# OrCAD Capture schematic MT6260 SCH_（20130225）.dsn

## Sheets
1 99==== Modification List: title: 99 Modify List; rev: V1.0; note: MT6260 PHONE
2 10==== PERI_Audio_USB11: size Custom; title: MT6260; rev: 1A; note: Audio_USB1.1
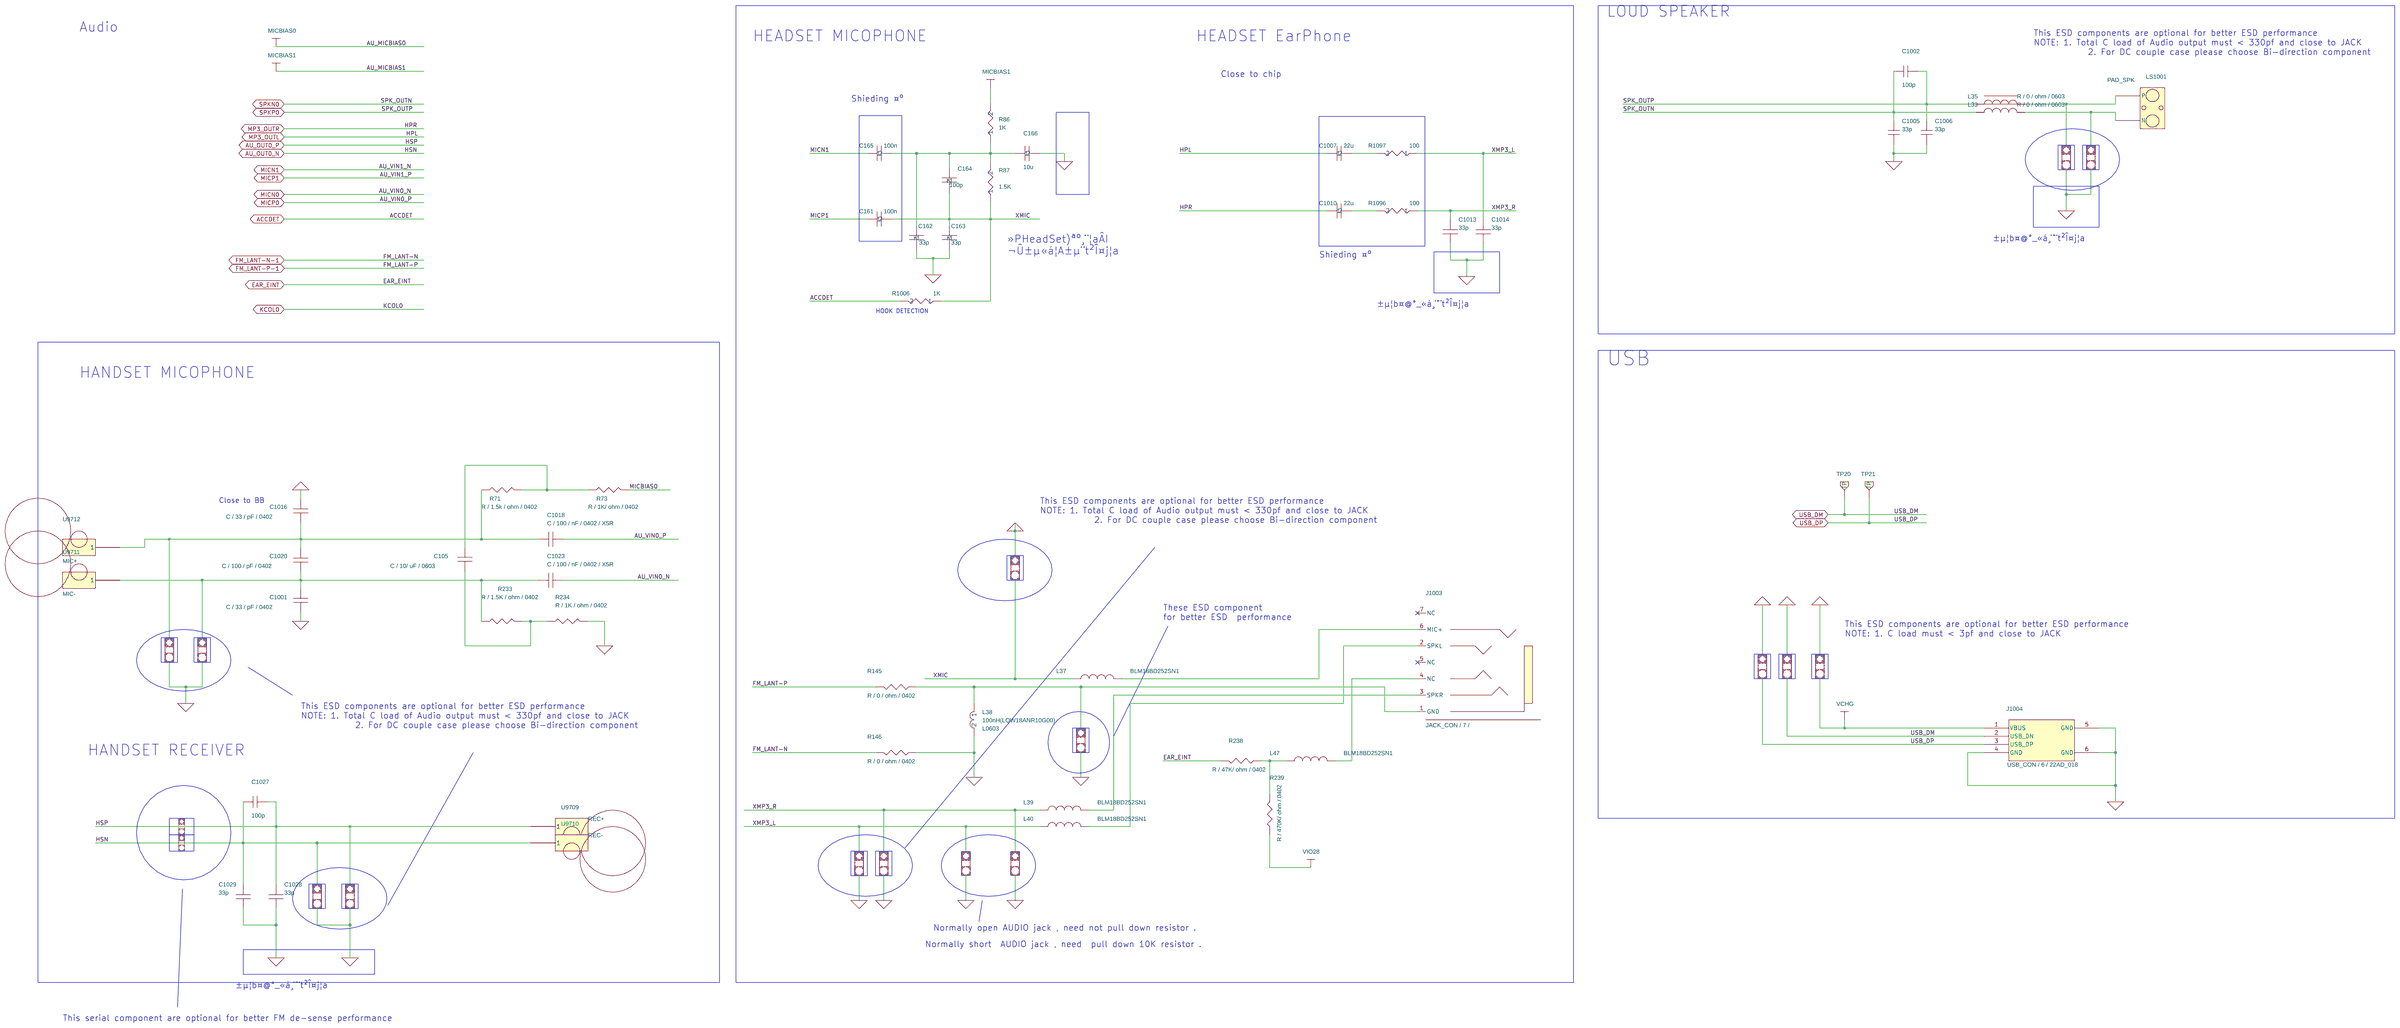
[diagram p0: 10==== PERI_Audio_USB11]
3 01==== History: title: Func. Owner List; rev: 1A; note: Baseband
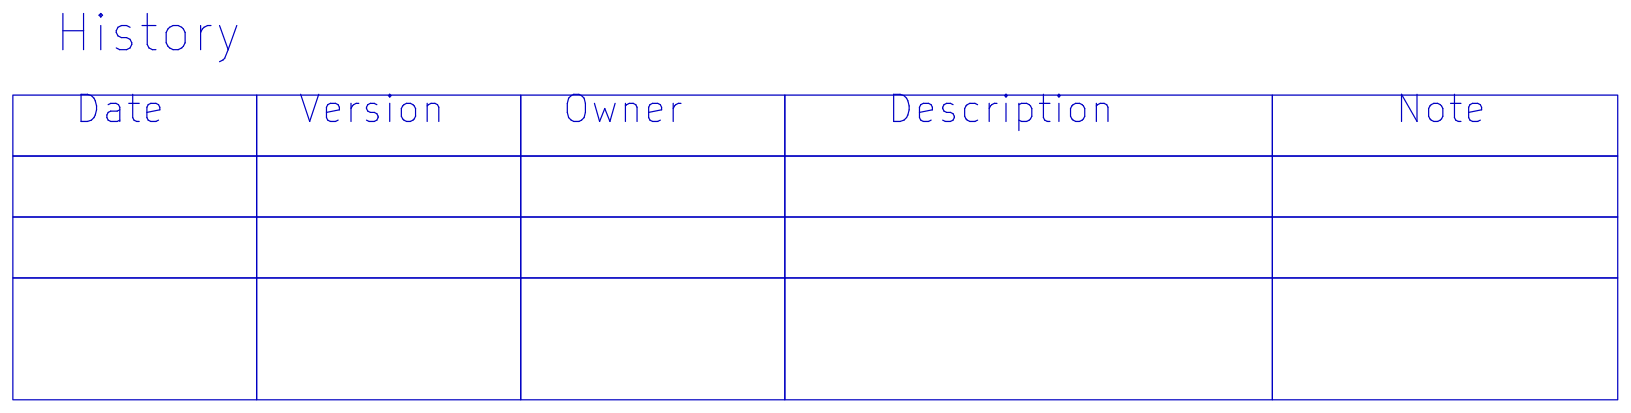
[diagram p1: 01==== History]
4 02==== MAIN_MT6260 BB: size Custom; title: MT6260; rev: 1A; note: Baseband
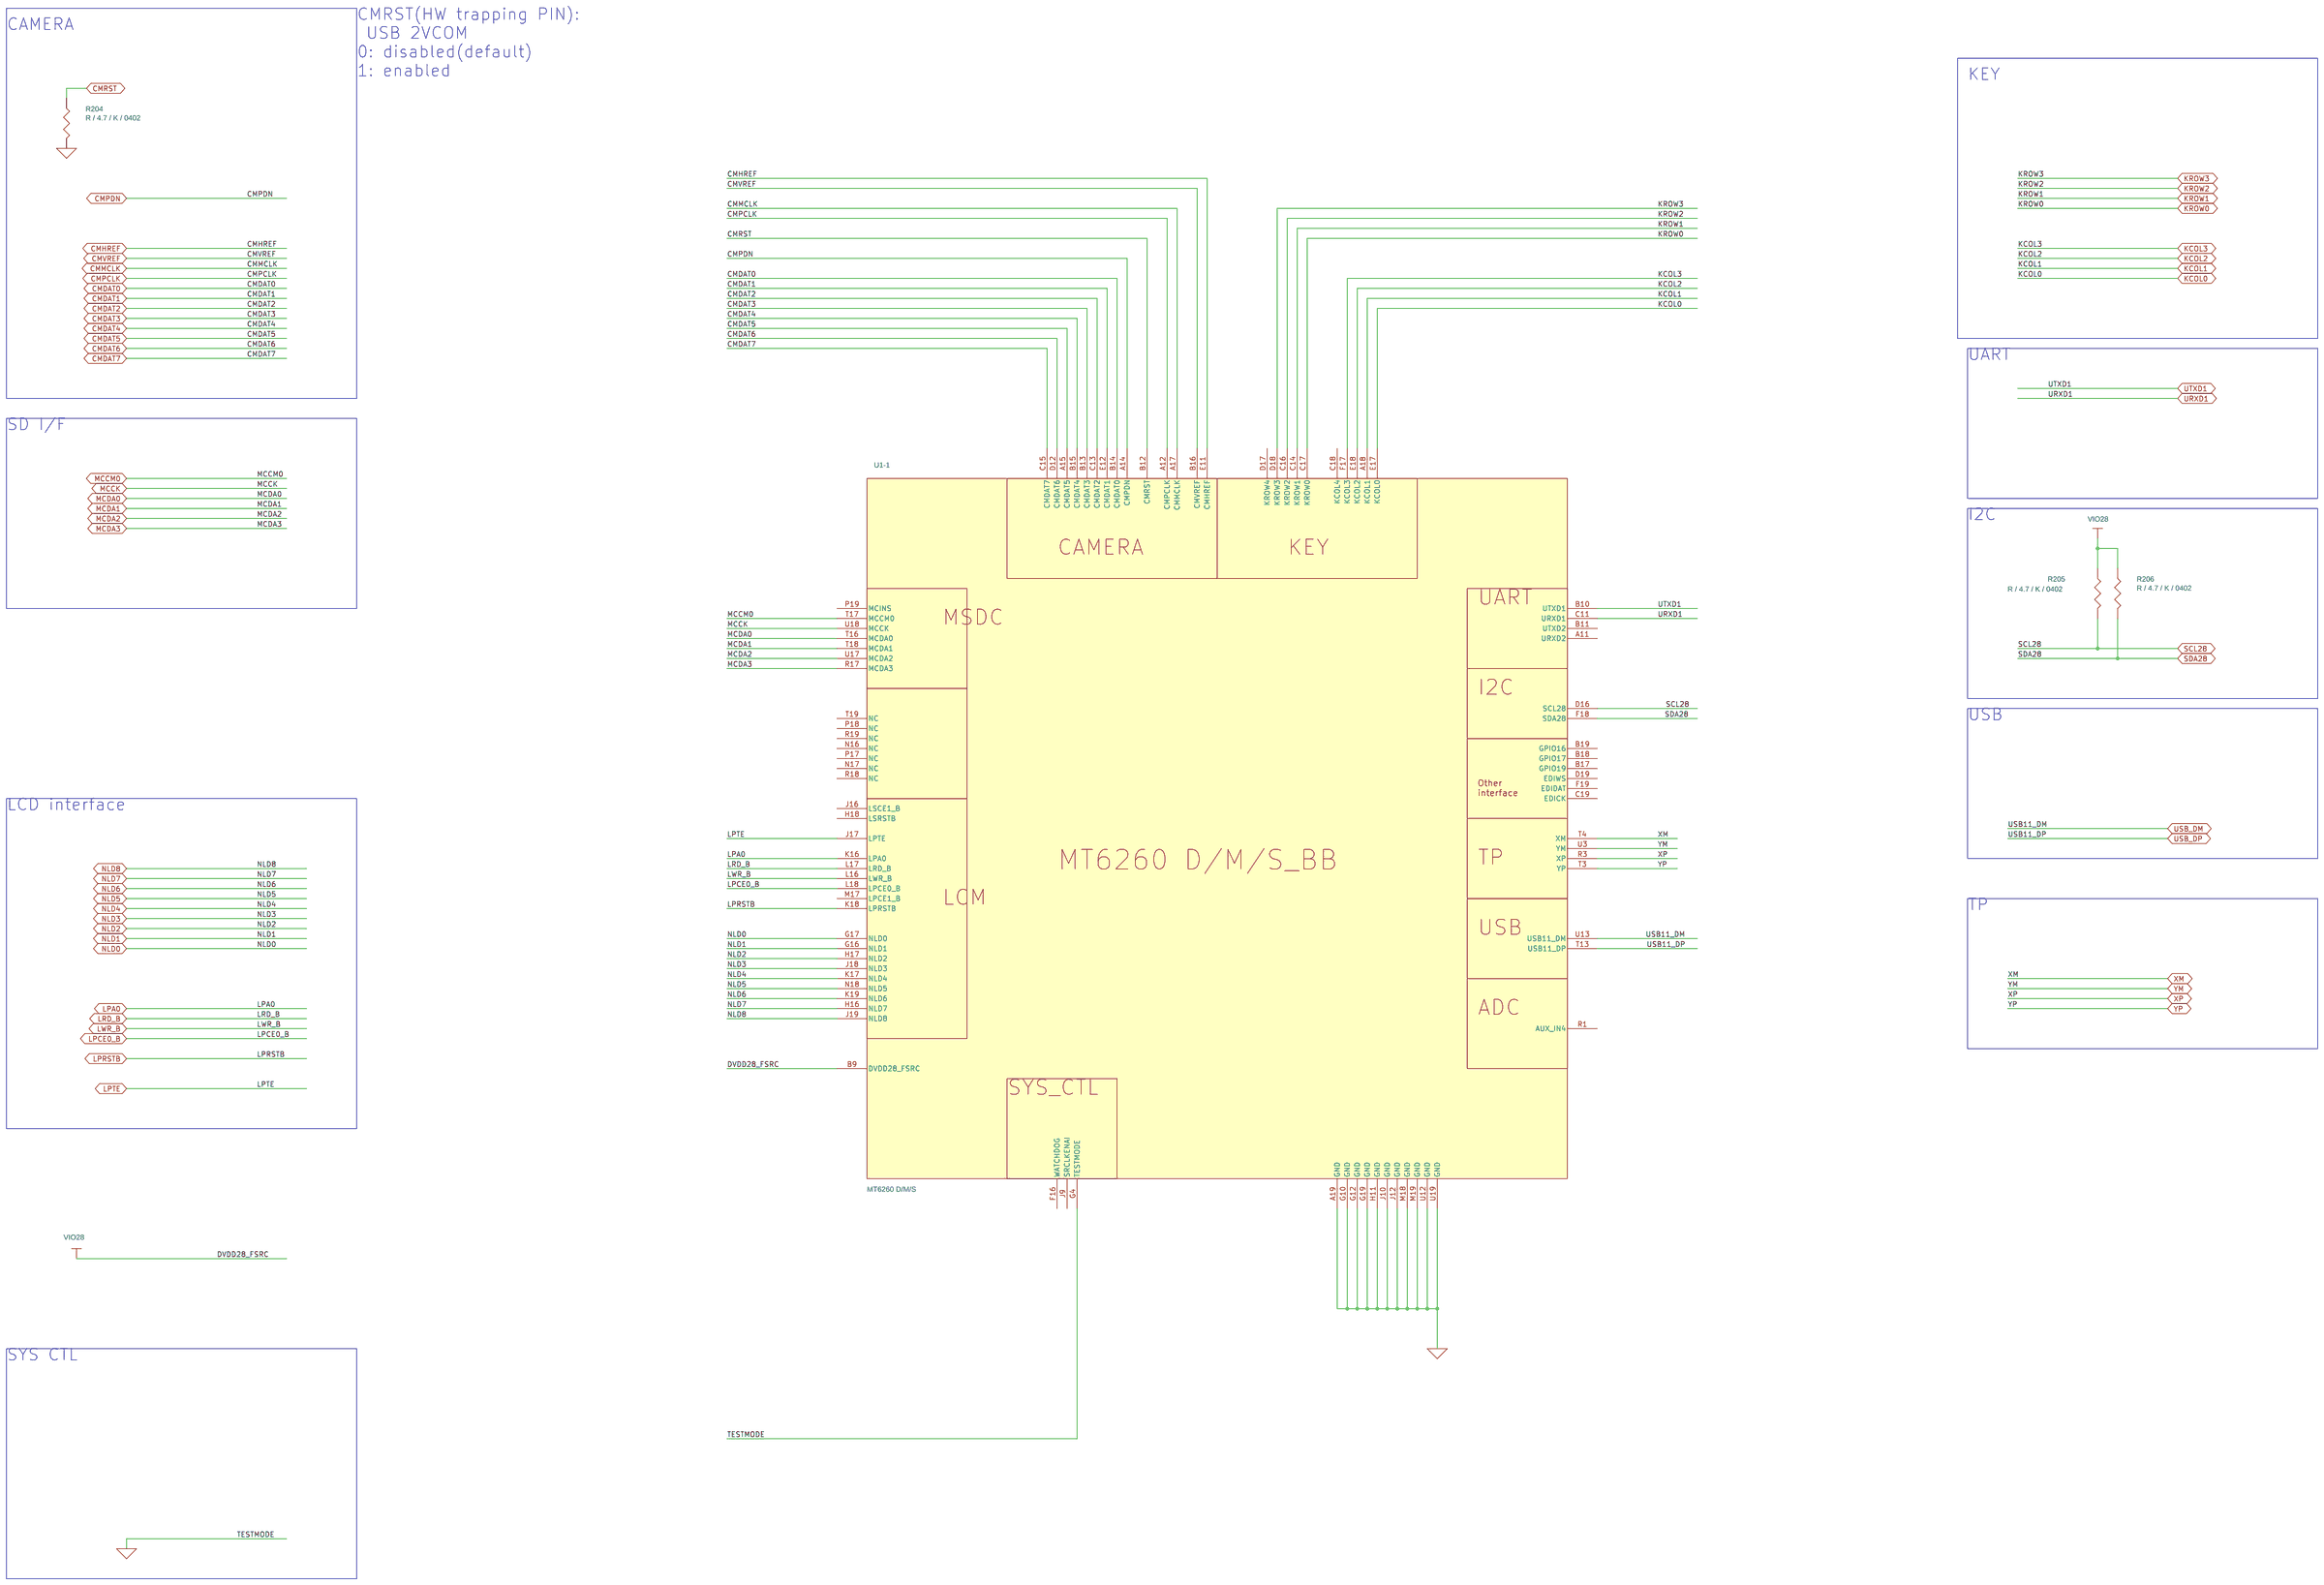
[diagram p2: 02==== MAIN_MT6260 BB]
5 03==== MAIN_MT6260 ABB: size Custom; title: MT6260; rev: 1A; note: ABB
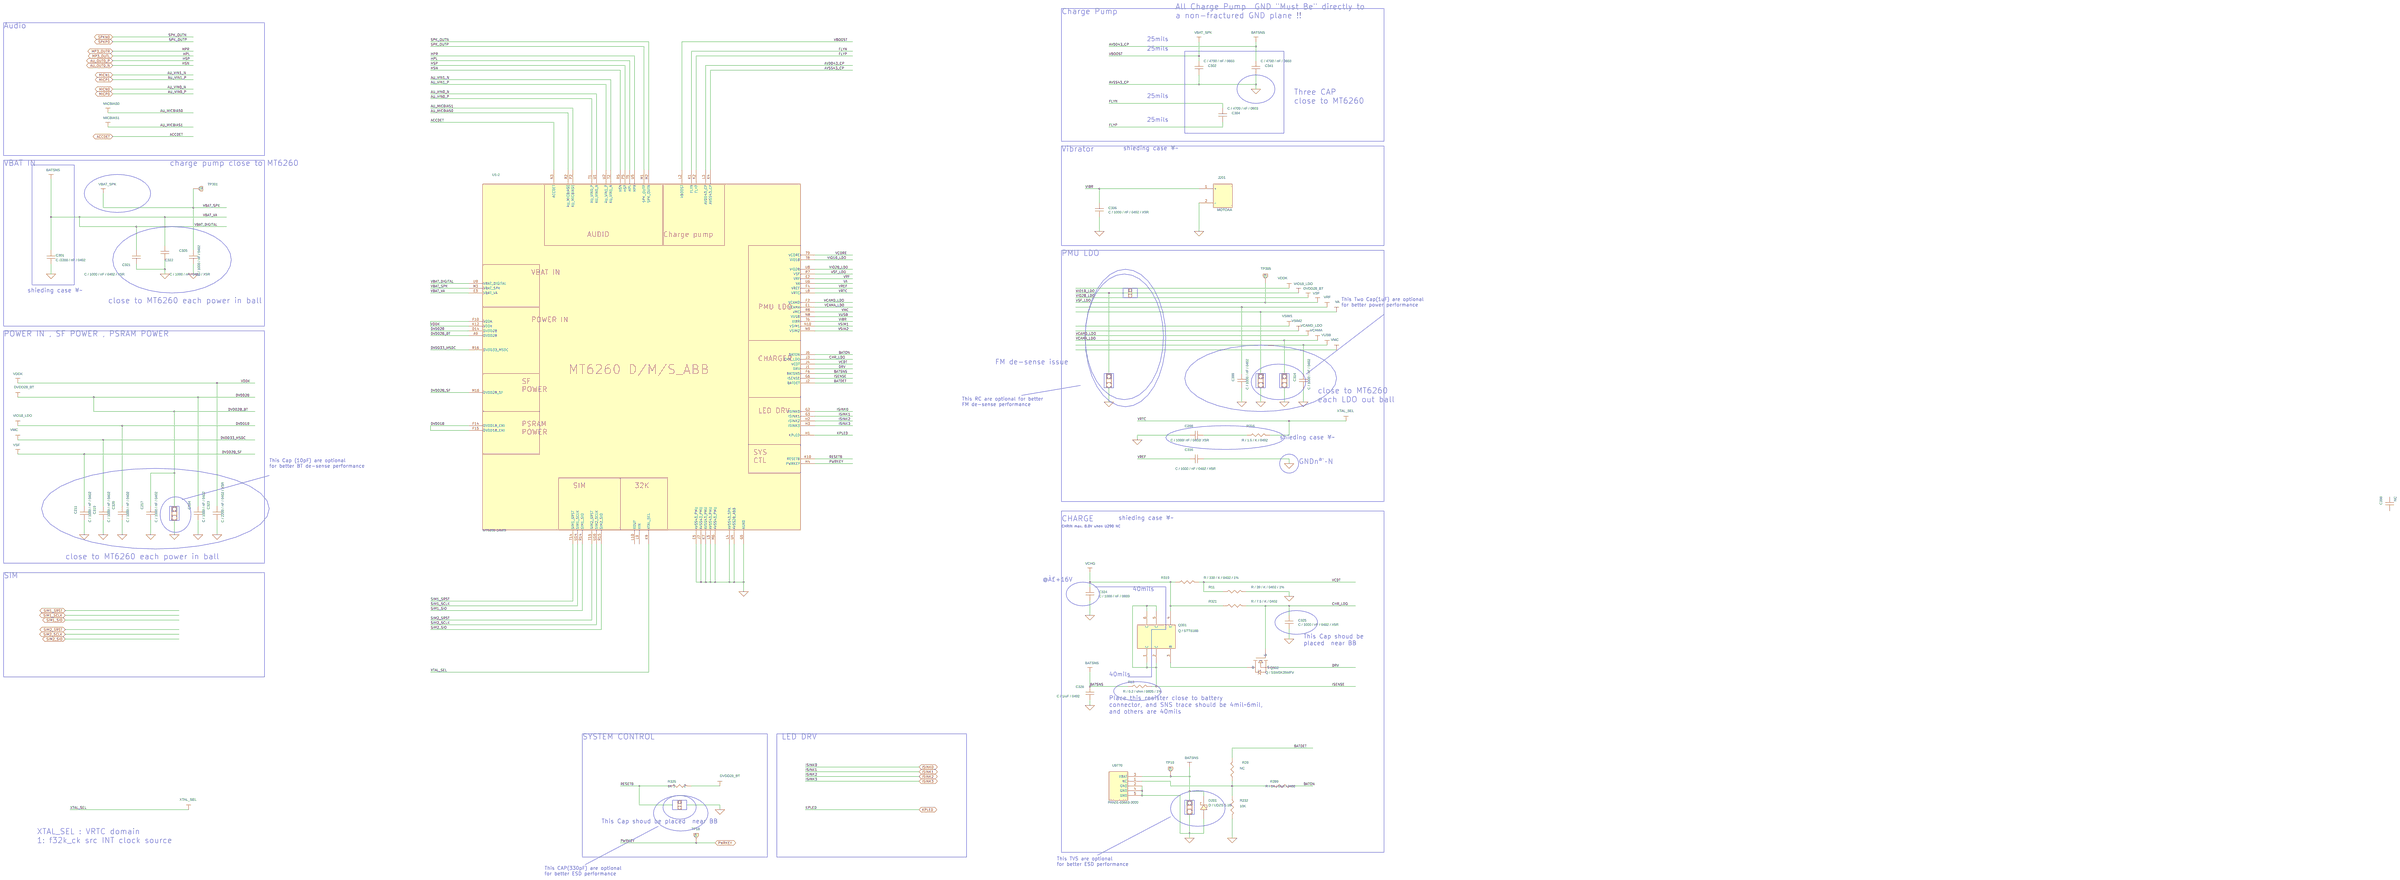
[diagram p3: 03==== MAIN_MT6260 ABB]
6 11==== PERI_SIM_T-Flash_Key: size Custom; title: MT6250; rev: 1A; note: SIM_T-Flash_Keypad
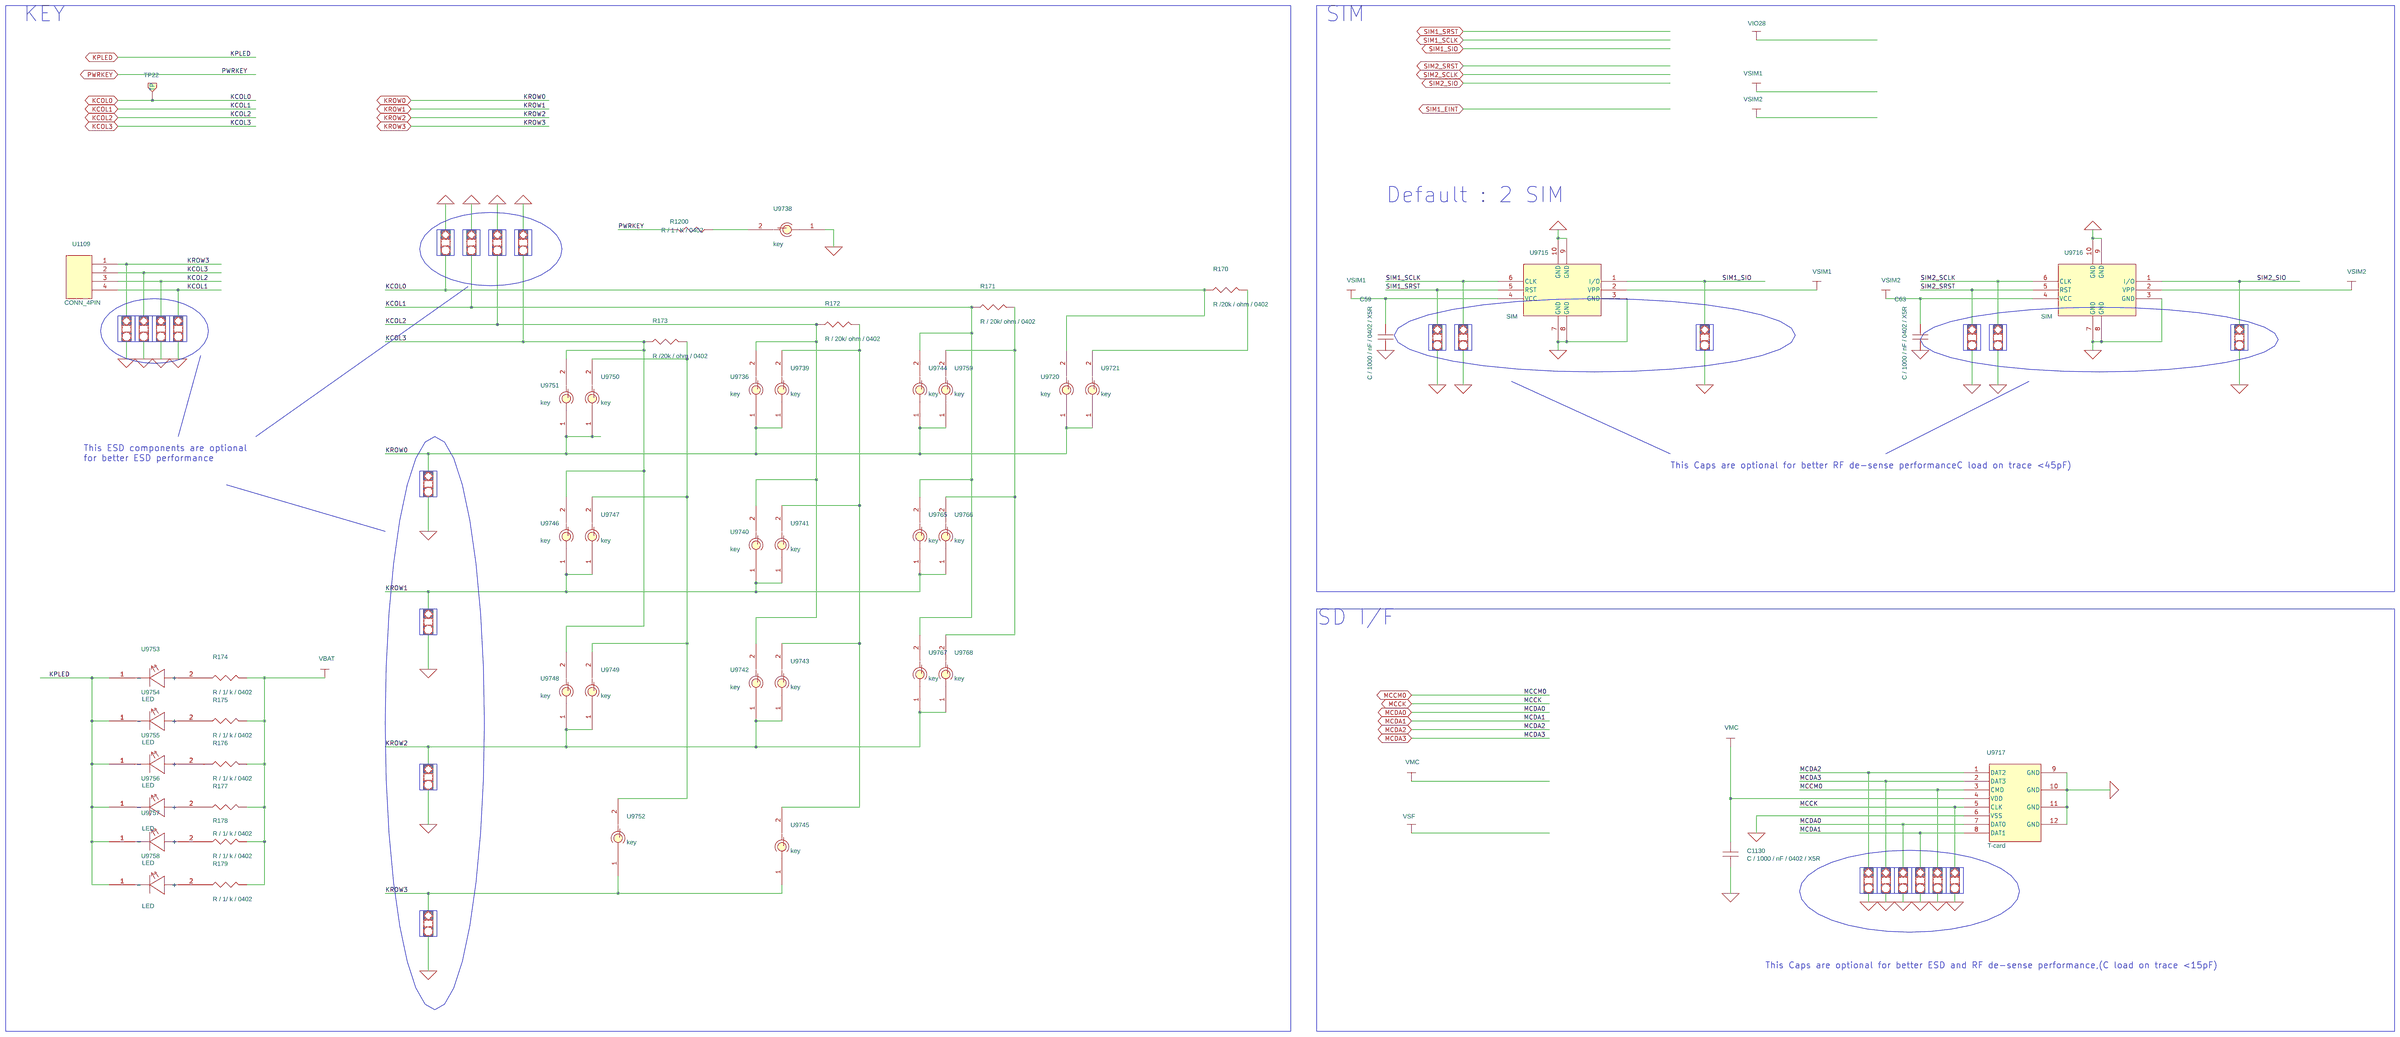
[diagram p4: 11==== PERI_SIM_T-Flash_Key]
7 09==== PERI_LCD_Camera: size A1; title: MT6260; rev: 1A; note: LCD_Camera_Audio_USB1.1
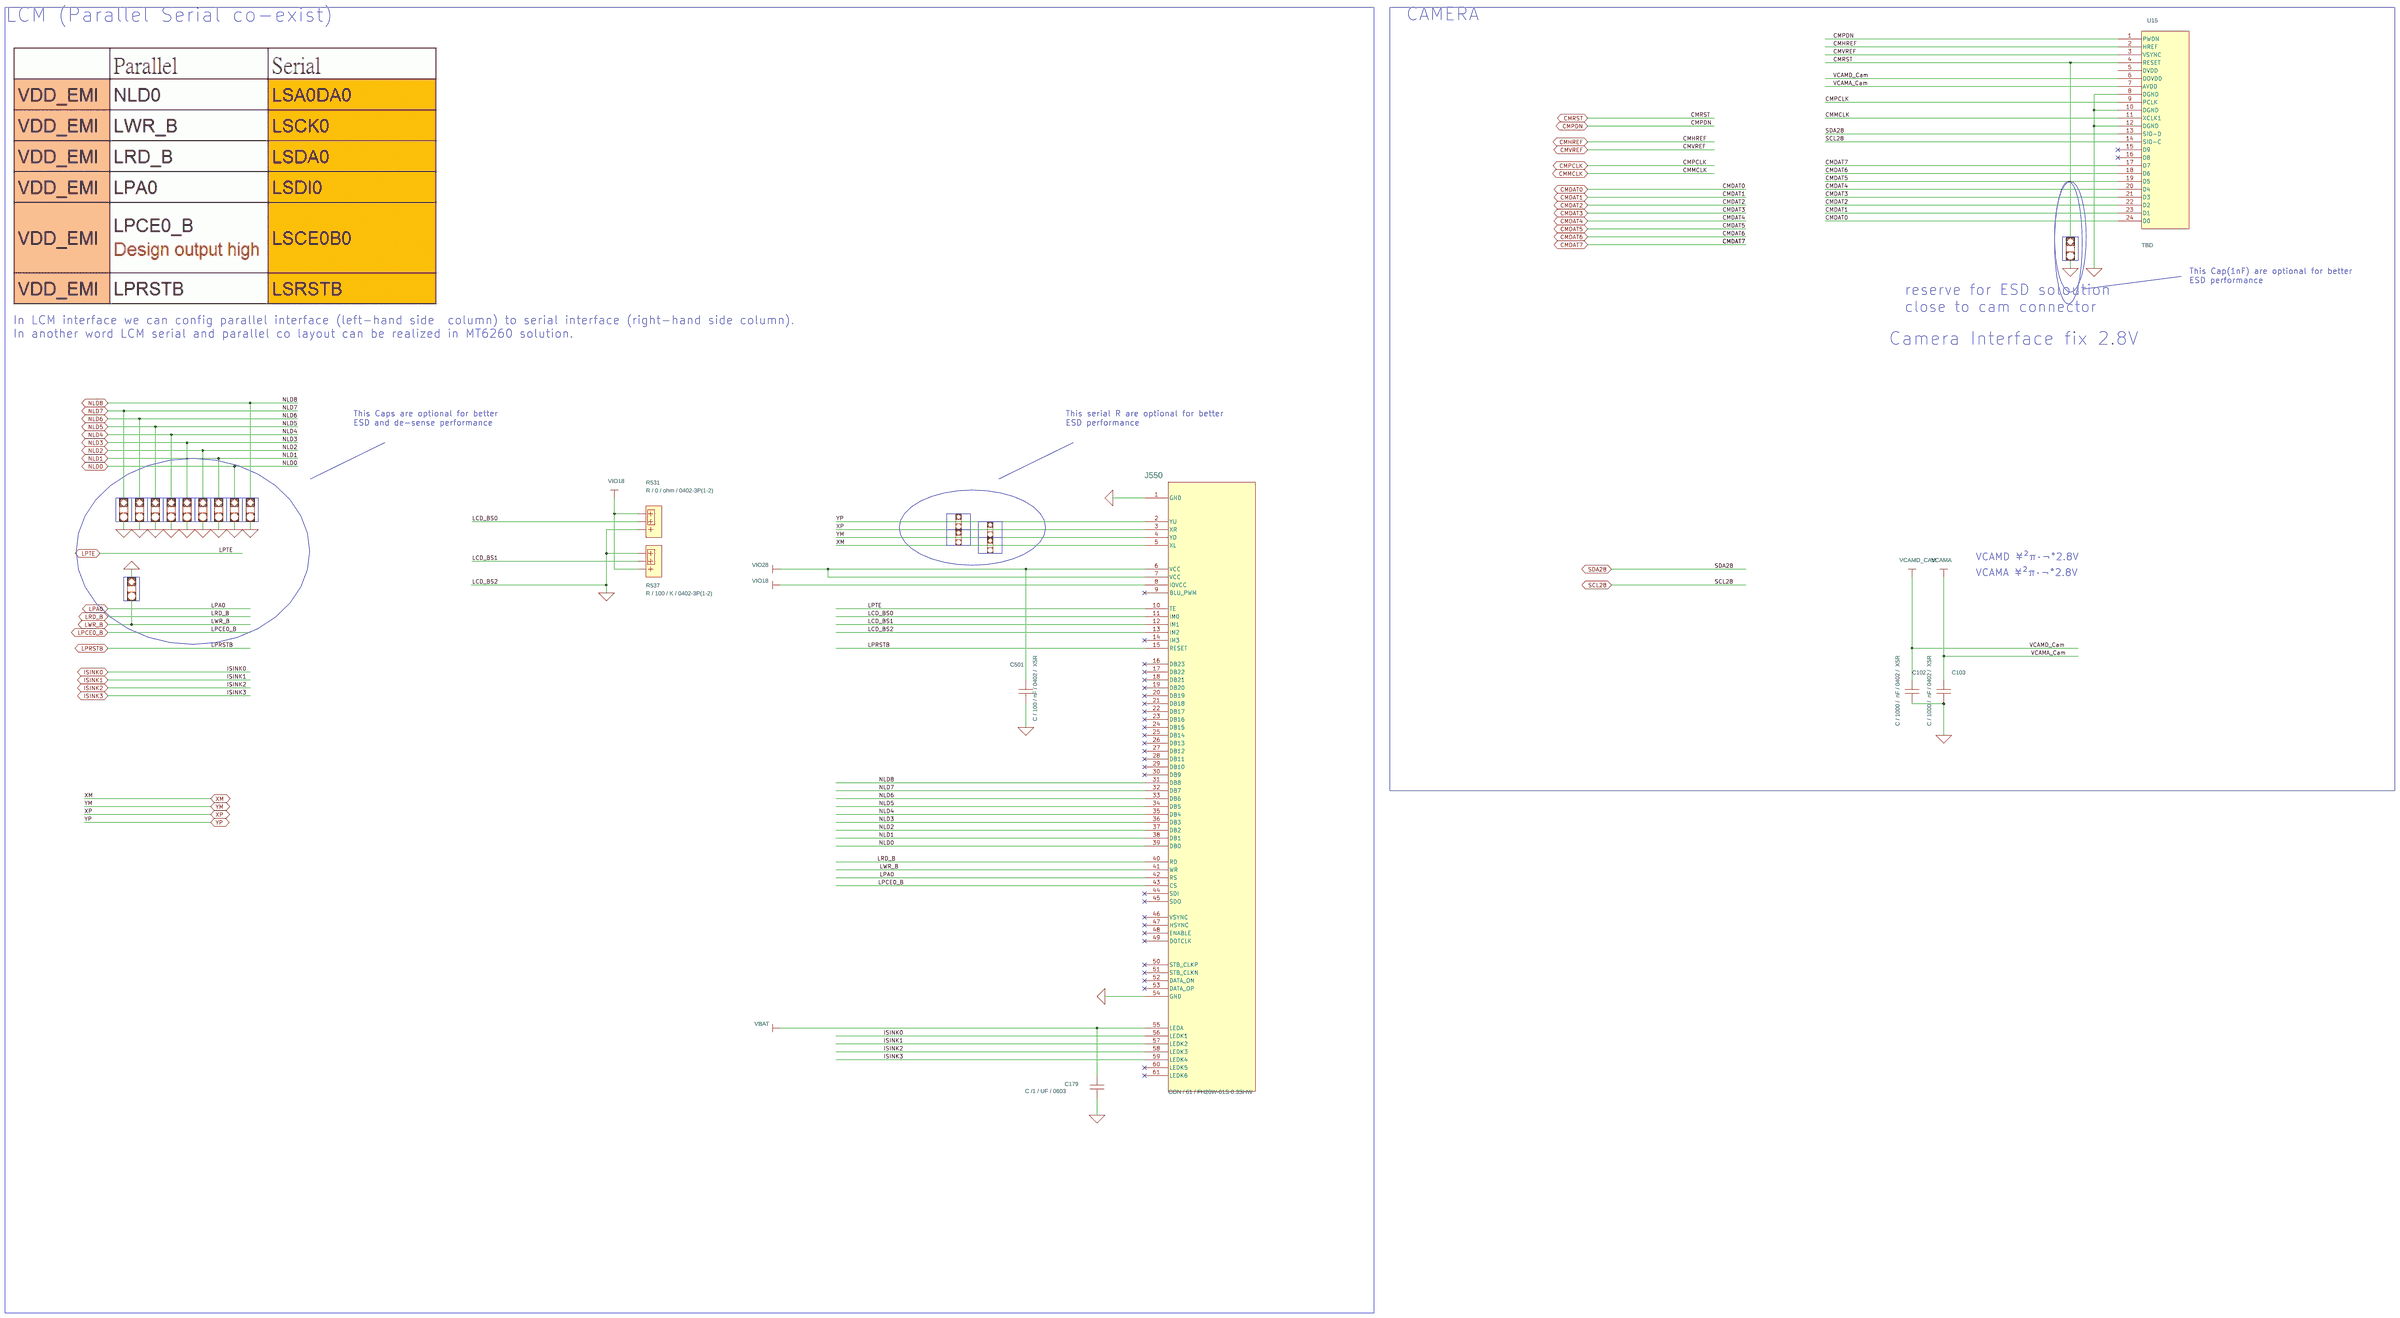
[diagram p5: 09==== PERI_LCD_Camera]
8 04==== MAIN_ MT6260 2G RF: size Custom; title: MT6260 RF; rev: 1A; note: 2G RF
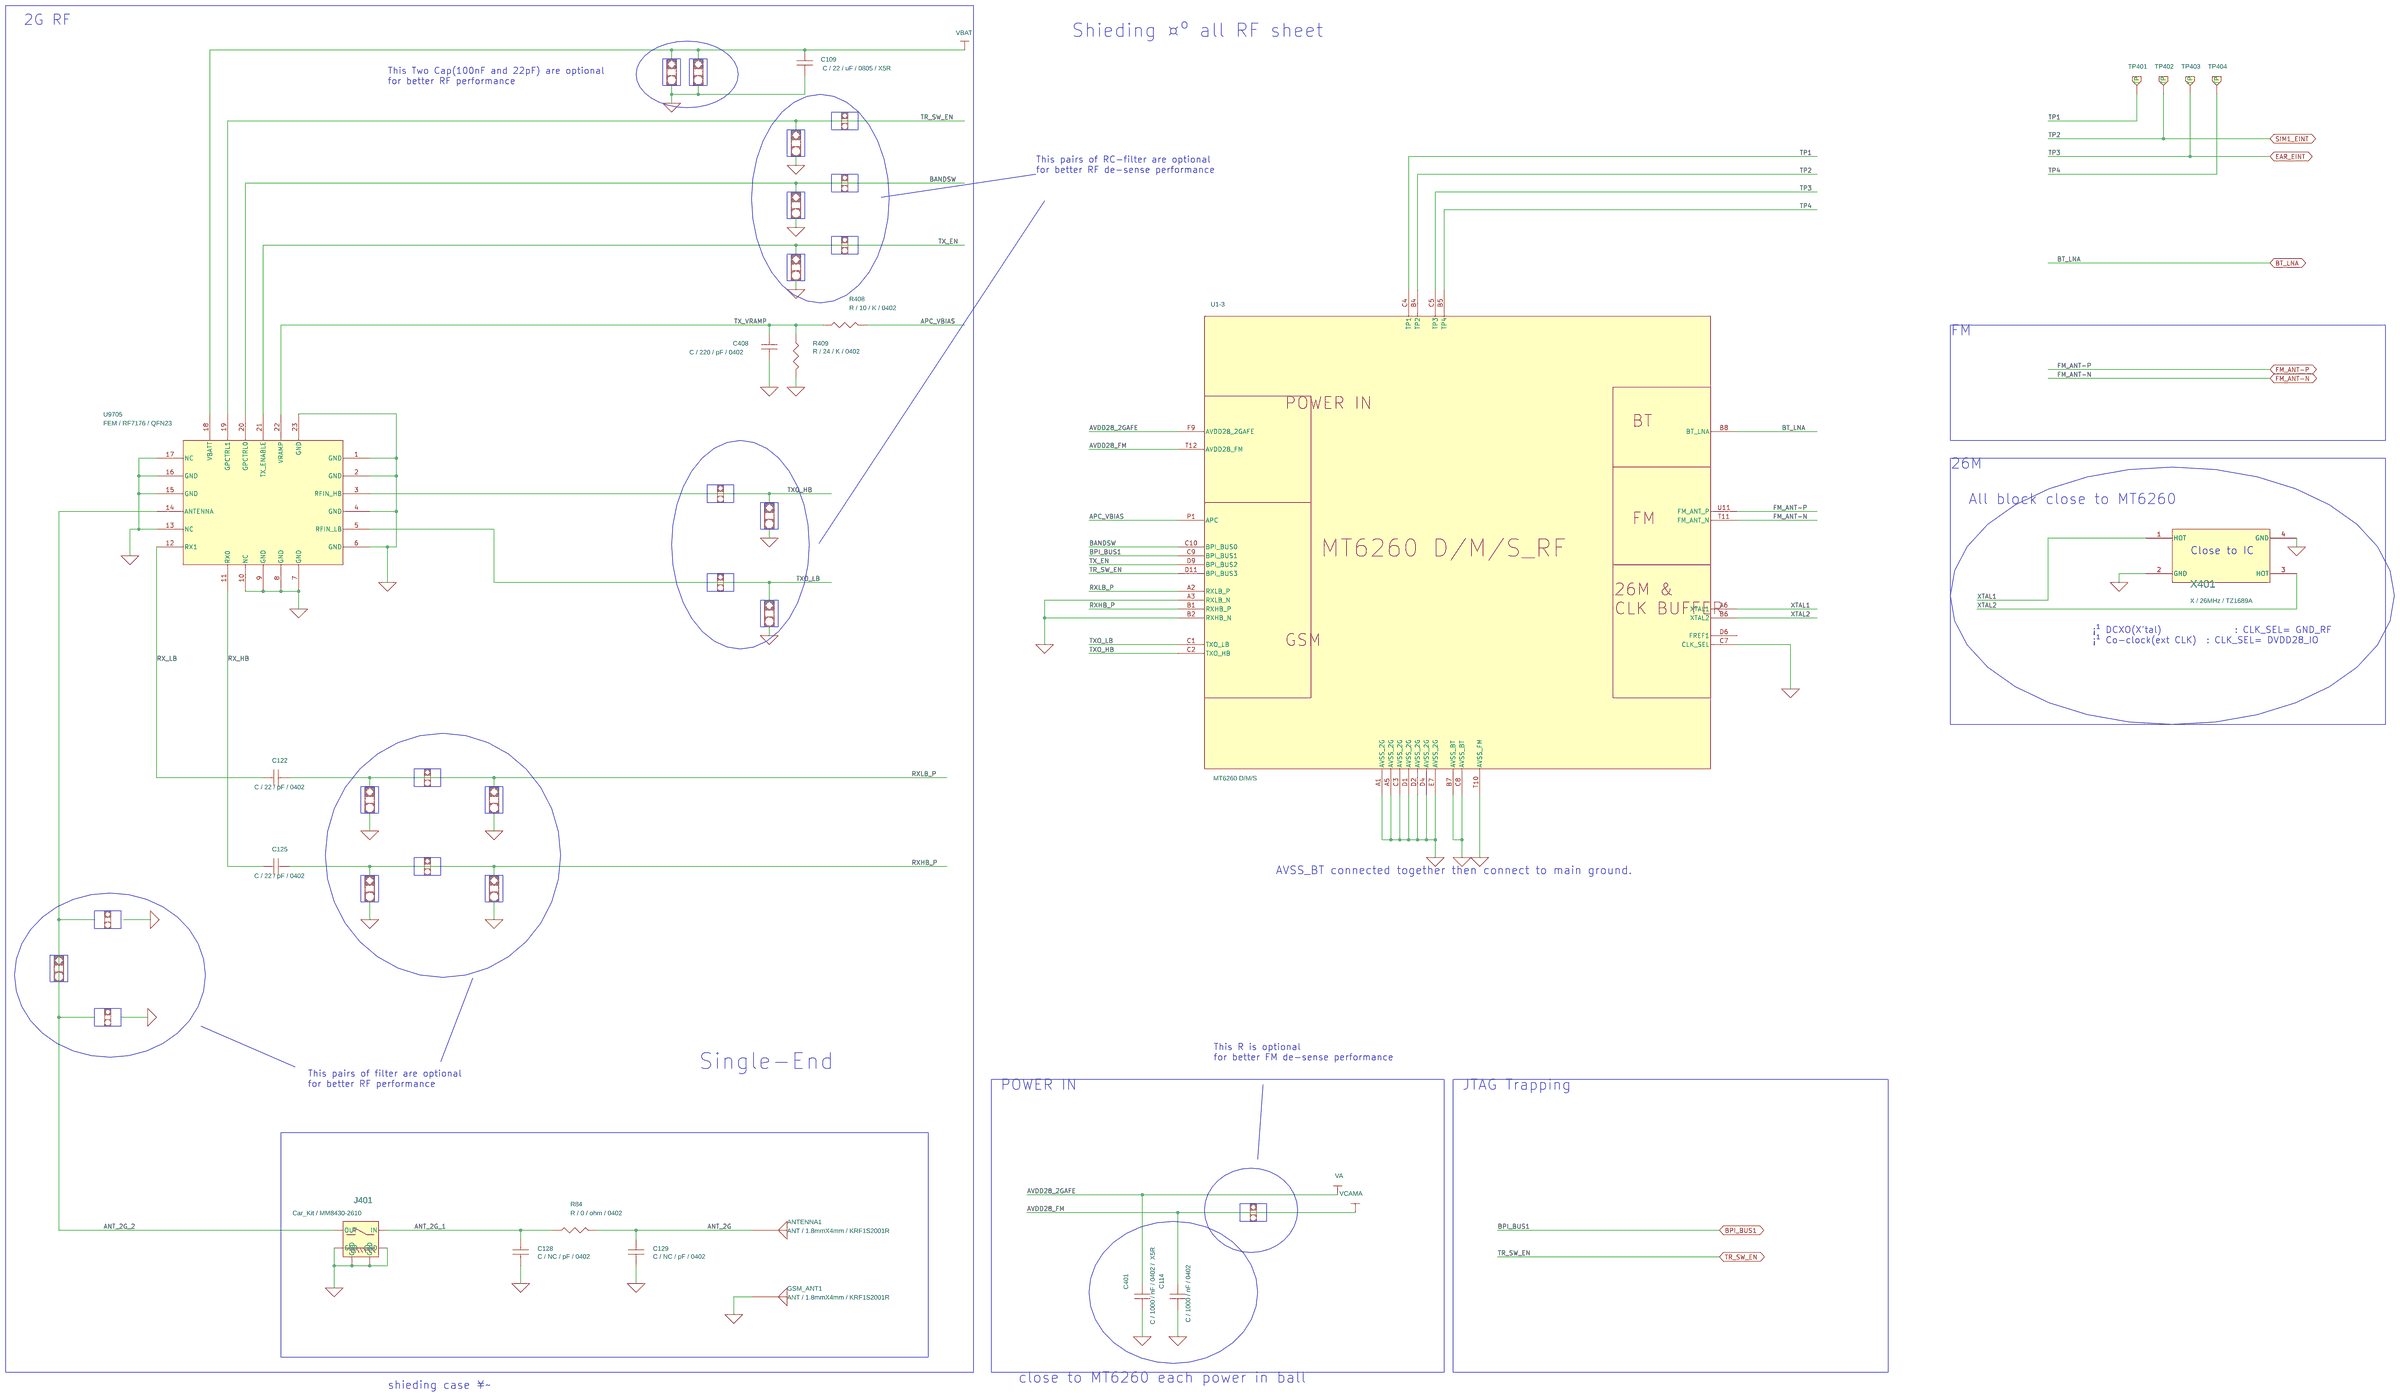
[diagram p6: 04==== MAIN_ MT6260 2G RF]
9 05==== MAIN_ FM RF CON: size A3; title: MT6260; rev: 0C; note: BT FM
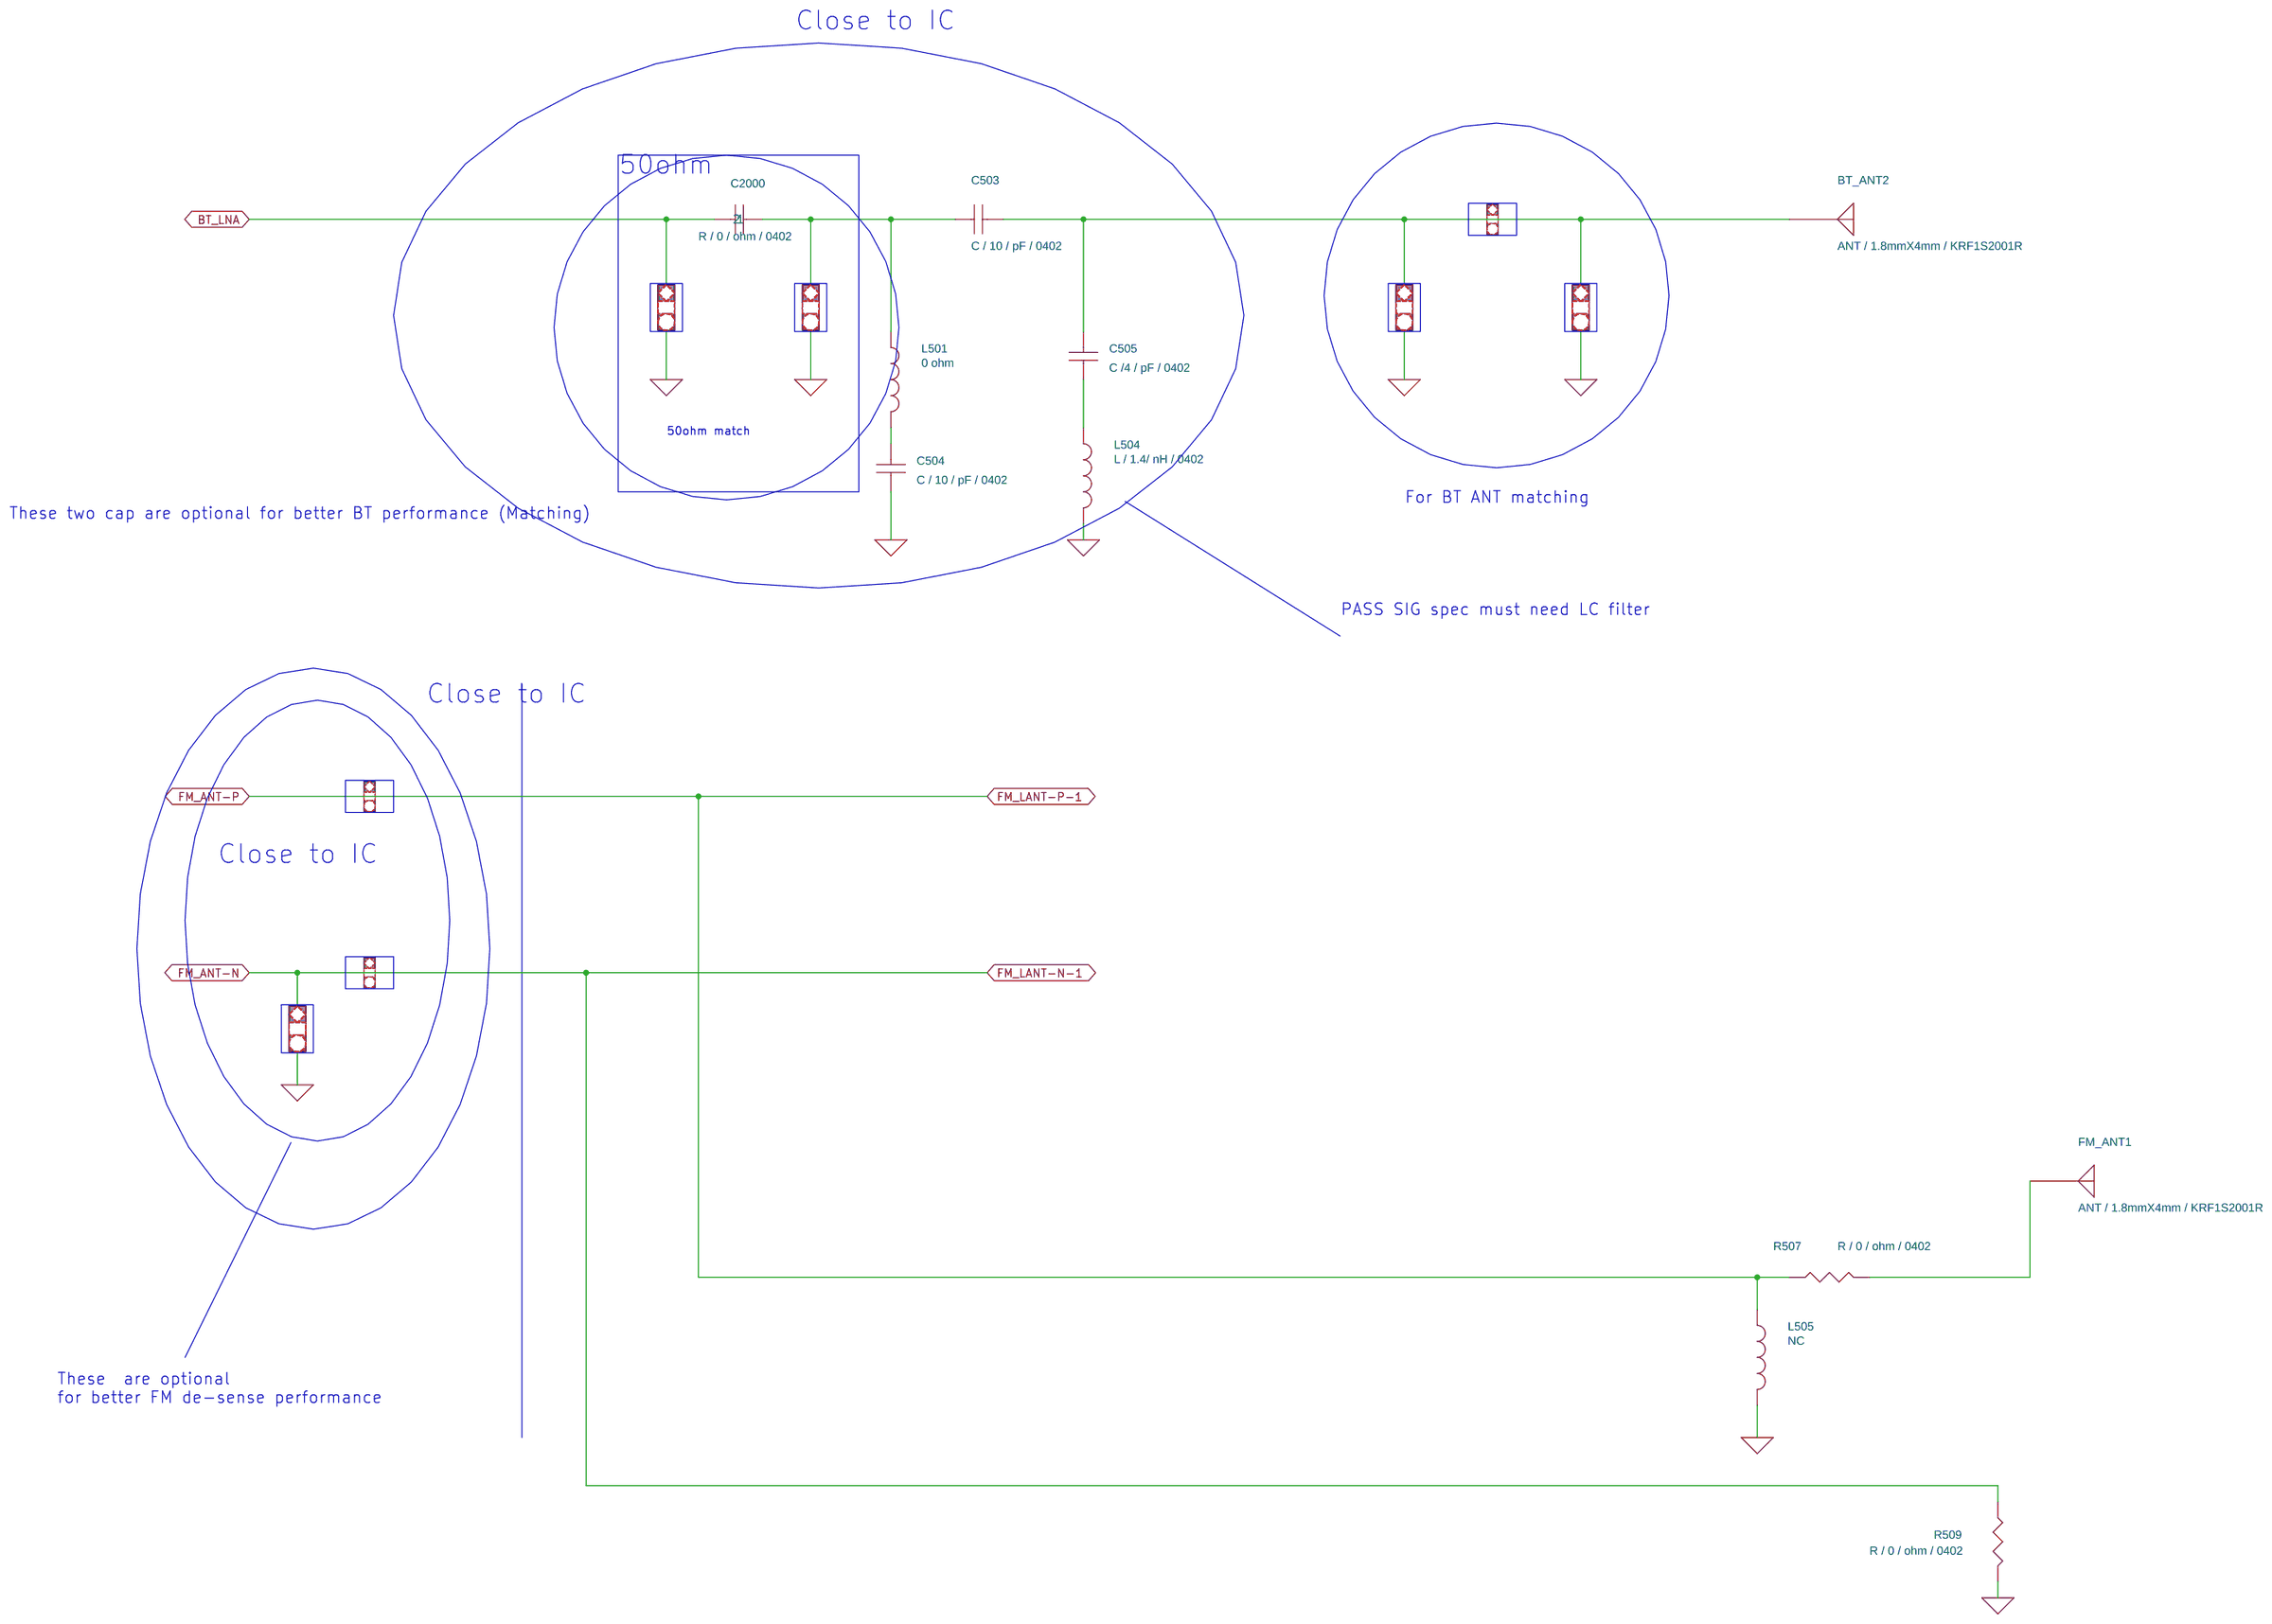
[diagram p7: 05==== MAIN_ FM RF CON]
10 97==== Debug Interface: size A2; title: MT6260; rev: 1A; note: Debug port
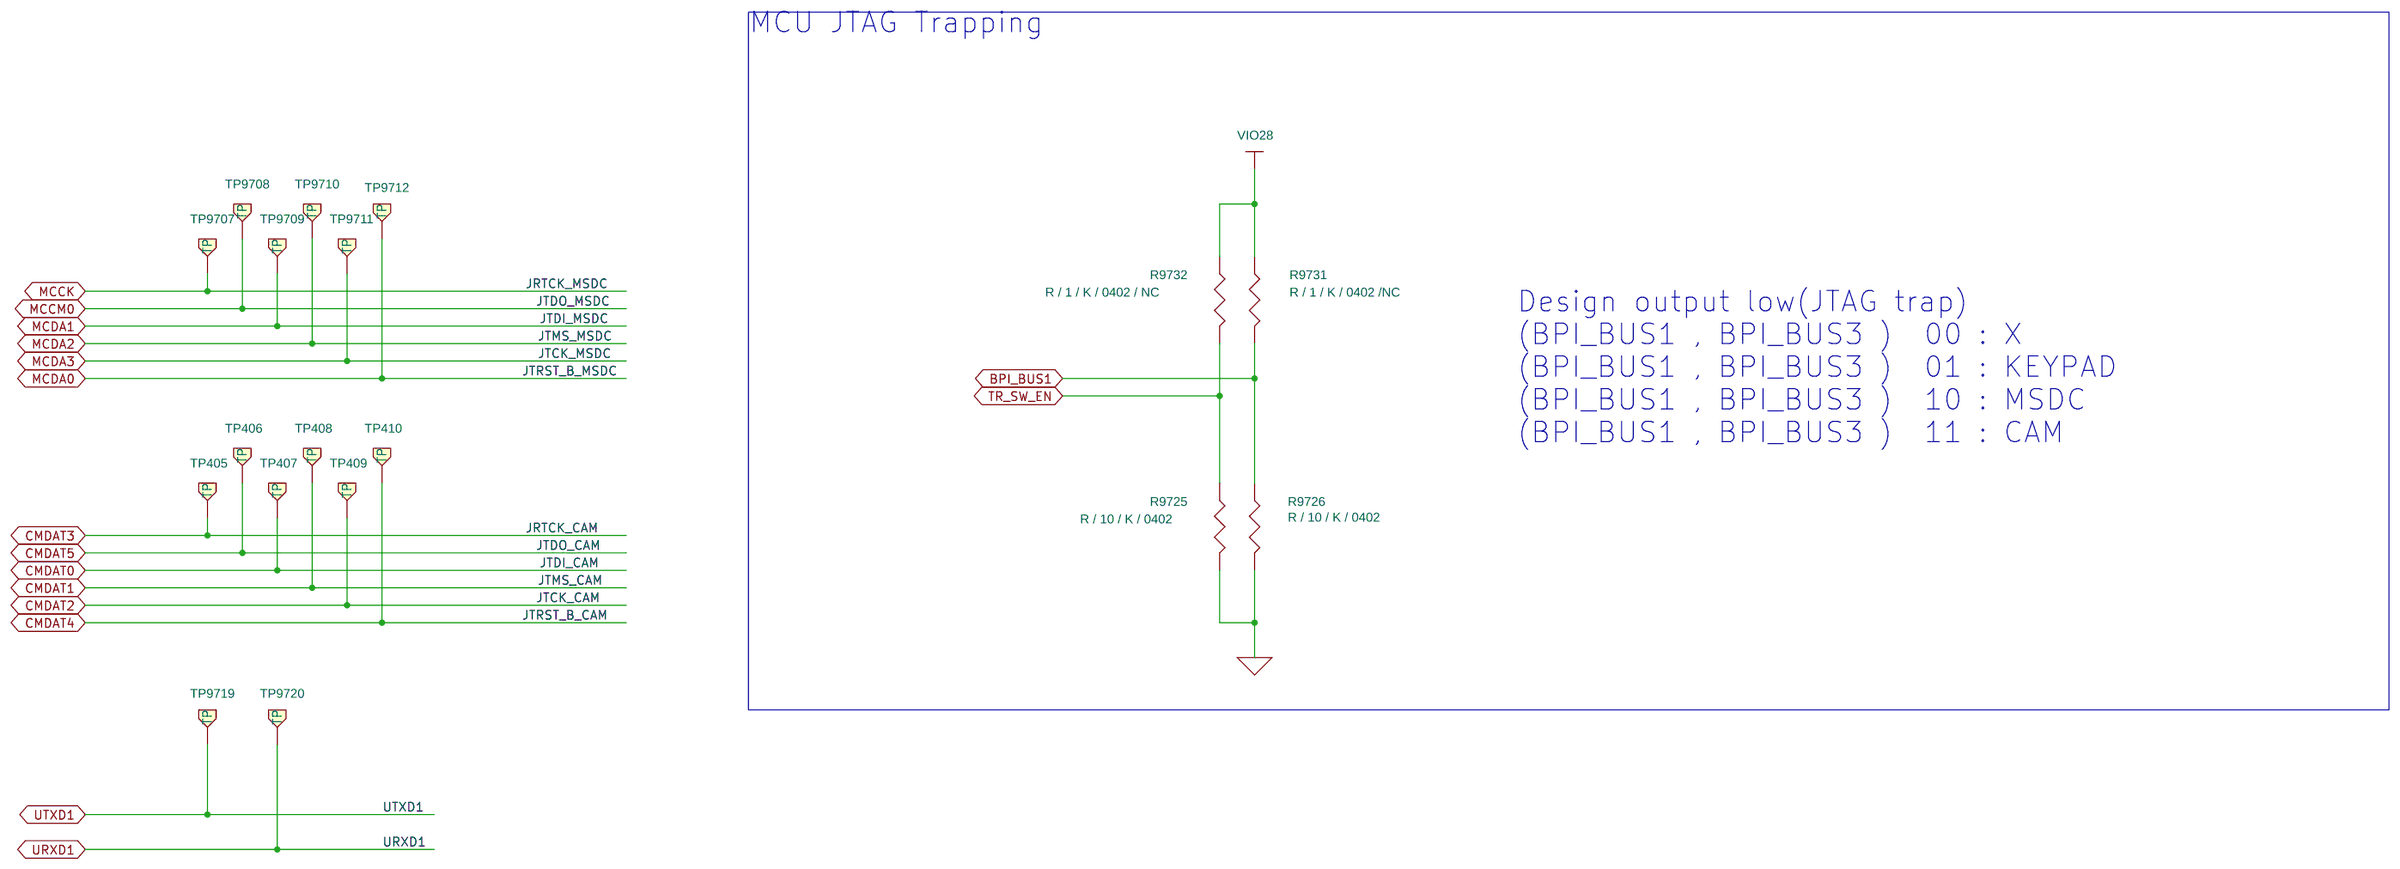
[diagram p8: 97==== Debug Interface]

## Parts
sheet 02==== MAIN_MT6260 BB
R204  R / 4.7 / K / 0402  [R0402]
R205  R / 4.7 / K / 0402  [R0402]
R206  R / 4.7 / K / 0402  [R0402]
sheet 03==== MAIN_MT6260 ABB
C208  C / 1000/ nF / 0402/ X5R  [C0402]
C211  C / 1000 / nF / 0402  [C0402]
C217  C / 1000 / nF / 0402  [C0402]
C301  C /2200 / nF / 0402  [C0402]
C302  C / 4700 / nF / 0603  [C0603]
C304  C / 4700 / nF / 0603  [C0603]
C305  C / 1000 / nF / 0402  [C0402]
C306  C / 1000 / nF / 0402 / X5R  [C0402]
C314  C / 1000 / nF / 0402  [C0402]
C316  C / 1000 / nF / 0402 / X5R  [C0402]
C319  C / 1000 / nF / 0402  [C0402]
C320  C / 1000 / nF / 0402  [C0402]
C321  C / 1000 / nF / 0402 / X5R  [C0402]
C322  C / 1000 / nF / 0402 / X5R  [C0402]
C323  C / 2200 / nF / 0402 / X5R  [C0402]
C324  C / 1000 / nF / 0603  [C0603]
C325  C / 1000 / nF / 0402 / X5R  [C0402]
C326  C / 1/uF / 0402  [C0402]
C341  C / 4700 / nF / 0603  [C0603]
C394  C / 1000 / nF / 0402  [C0402]
C398  NC  [C0402]
C399  C / 1000 / nF / 0402  [C0402]
D201  D / UDZS 5.1B  [SOD323]
J201  MOTOAA  [MOTOAA]
Q301  Q / STT818B  [SOT-6]
Q302  Q / SSM3K35MFV  [2-1L1B/SMD/SSM3K35MFV]
R11  R / 39 / K / 0402 / 1%  [R0402]
R13  R / 0.2 / ohm / 0805 / 1%  [R0805]
R28  NC  [R0402]
R232  10K  [R0402]
R316  R / 1.5 / K / 0402  [R0402]
R319  R / 330 / K / 0402 / 1%  [R0402]
R321  R / 7.5 / K / 0402  [R0402]
R325  1K  [R0402]
R399  R / 1K / ohm / 0402  [R0402]
TP18  NC  [TP_2.4A]
TP19  NC  [TP_2.4A]
TP301  NC  [TP/SMD/0.5MM]
TP305  NC  [TP/SMD/0.5MM]
U9770  PAN31-03683-3000  [B03-AB03FXX0A]
sheet 04==== MAIN_ MT6260 2G RF
ANTENNA1  ANT / 1.8mmX4mm / KRF1S2001R  [ANTENNAB]
C109  C / 22 / uF / 0805 / X5R  [C0805]
C114  C / 1000 / nF / 0402  [C0402]
C122  C / 22 / pF / 0402  [C0402]
C125  C / 22 / pF / 0402  [C0402]
C128  C / NC / pF / 0402  [C0402]
C129  C / NC / pF / 0402  [C0402]
C401  C / 1000 / nF / 0402 /  X5R  [C0402]
C408  C / 220 / pF / 0402  [C0402]
GSM_ANT1  ANT / 1.8mmX4mm / KRF1S2001R  [ANTENNAB]
J401  Car_Kit / MM8430-2610  [MM8430-2600B]
R84  R / 0 / ohm / 0402  [R0402]
R408  R / 10 / K / 0402  [R0402]
R409  R / 24 / K / 0402  [R0402]
TP401  NC_TP30MIL  [TP20MIL]
TP402  NC_TP30MIL  [TP20MIL]
TP403  NC_TP30MIL  [TP20MIL]
TP404  NC_TP30MIL  [TP20MIL]
U1  MT6260 D/M/S  (sections -1,-2,-3)
U9705  FEM / RF7176 / QFN23  [RF7170]
X401  X / 26MHz / TZ1689A  [TCXO3225]
sheet 05==== MAIN_ FM RF CON
BT_ANT2  ANT / 1.8mmX4mm / KRF1S2001R  [ANTENNAC]
C503  C / 10 / pF / 0402  [C0402]
C504  C / 10 / pF / 0402  [C0402]
C505  C /4 / pF / 0402  [C0402]
C2000  R / 0 / ohm / 0402  [C0402]
FM_ANT1  ANT / 1.8mmX4mm / KRF1S2001R  [ANTENNAC]
L501  0 ohm  [0402]
L504  L / 1.4/ nH / 0402  [0402]
L505  NC  [L0603]
R507  R / 0 / ohm / 0402  [R0402]
R509  R / 0 / ohm / 0402  [R0402]
sheet 09==== PERI_LCD_Camera
C102  C / 1000 /  nF / 0402 /  X5R  [C0402]
C103  C / 1000 /  nF / 0402 /  X5R  [C0402]
C179  C /1 / UF / 0603  [C0603]
C501  C / 100 / nF / 0402 /  X5R  [C0402]
J550  CON / 61 / FH26W-61S-0.3SHW  [H61/SMD/FH26-61S-0.3SHW/A]
R531  R / 0 / ohm / 0402-3P(1-2)  [0402-3P(1-2)]
R537  R / 100 / K / 0402-3P(1-2)  [0402-3P(1-2)]
U15  TBD  [DF30FC-24DS-0.4V]
sheet 10==== PERI_Audio_USB11
C105  C / 10/ uF / 0603  [C0603]
C161  100n  [C0402]
C162  33p  [C0402]
C163  33p  [C0402]
C164  100p  [C0402]
C165  100n  [C0402]
C166  10u  [C0603]
C1001  C / 33 / pF / 0402  [C0402]
C1002  100p  [C0402]
C1005  33p  [C0402]
C1006  33p  [C0402]
C1007  22u  [C0805]
C1010  22u  [C0805]
C1013  33p  [C0402]
C1014  33p  [C0402]
C1016  C / 33 / pF / 0402  [C0402]
C1018  C / 100 / nF / 0402 / X5R  [C0402]
C1020  C / 100 / pF / 0402  [C0402]
C1023  C / 100 / nF / 0402 / X5R  [C0402]
C1027  100p  [C0402]
C1028  33p  [C0402]
C1029  33p  [C0402]
J1003  JACK_CON / 7 /  [AUDIOJACK/6P/SMD/KJA1339C01R]
J1004  USB_CON / 6 / 22AD_018  [MINIUSB(Y16-102)]
L33  R / 0 / ohm / 0603  [L0603]
L35  R / 0 / ohm / 0603  [L0603]
L37  BLM18BD252SN1  [C0402]
L38  100nH(LQW18ANR10G00)  [L0603]
L39  BLM18BD252SN1  [C0402]
L40  BLM18BD252SN1  [C0402]
L47  BLM18BD252SN1  [C0402]
LS1001  PAD_SPK  [PAD_SPK]
R71  R / 1.5k / ohm / 0402  [R0402]
R73  R / 1K/ ohm / 0402  [R0402]
R86  1K  [R0402]
R87  1.5K  [R0402]
R145  R / 0 / ohm / 0402  [R0402]
R146  R / 0 / ohm / 0402  [R0402]
R233  R / 1.5K / ohm / 0402  [R0402]
R234  R / 1K / ohm / 0402  [R0402]
R238  R / 47K/ ohm / 0402  [R0402]
R239  R / 470K/ ohm / 0402  [R0402]
R1006  1K  [R0402]
R1096  100  [R0402]
R1097  100  [R0402]
TP20  NC  [TP_2.4A]
TP21  NC  [TP_2.4A]
U9709  REC+  [TP_3X5.4BAAA]
U9710  REC-  [TP_3X5.4BAAA]
U9711  MIC-  [PAD_0.8X1.8]
U9712  MIC+  [PAD_0.8X1.8]
sheet 11==== PERI_SIM_T-Flash_Key
C59  C / 1000 / nF / 0402 / X5R  [C0402]
C63  C / 1000 / nF / 0402 / X5R  [C0402]
C1130  C / 1000 / nF / 0402 / X5R  [C0402]
R170  R /20k / ohm / 0402  [R0402]
R171  R / 20k/ ohm / 0402  [R0402]
R172  R / 20k/ ohm / 0402  [R0402]
R173  R /20k / ohm / 0402  [R0402]
R174  R / 1/ k / 0402  [R0402]
R175  R / 1/ k / 0402  [R0402]
R176  R / 1/ k / 0402  [R0402]
R177  R / 1/ k / 0402  [R0402]
R178  R / 1/ k / 0402  [R0402]
R179  R / 1/ k / 0402  [R0402]
R1200  R / 1 / K / 0402  [R0402]
TP22  NC  [TP_2.4A]
U1109  CONN_4PIN  [CONN_4PIN]
U9715  SIM  [SIMMS-00615-TP32]
U9716  SIM  [SIMMS-00615-TP32]
U9717  T-card  [CAH11-08193-1500]
U9720  key  [KEY_5X4]
U9721  key  [KEY_5X4]
U9736  key  [KEY_5X4]
U9738  key  [KEY_5X4]
U9739  key  [KEY_5X4]
U9740  key  [KEY_5X4]
U9741  key  [KEY_5X4]
U9742  key  [KEY_5X4]
U9743  key  [KEY_5X4]
U9744  key  [KEY_5X4]
U9745  key  [KEY_5X4]
U9746  key  [KEY_5X4]
U9747  key  [KEY_5X4]
U9748  key  [KEY_5X4]
U9749  key  [KEY_5X4]
U9750  key  [KEY_5X4]
U9751  key  [KEY_5X4]
U9752  key  [KEY_5X4]
U9753  LED  [LED-0603]
U9754  LED  [LED-0603]
U9755  LED  [LED-0603]
U9756  LED  [LED-0603]
U9757  LED  [LED-0603]
U9758  LED  [LED-0603]
U9759  key  [KEY_5X4]
U9765  key  [KEY_5X4]
U9766  key  [KEY_5X4]
U9767  key  [KEY_5X4]
U9768  key  [KEY_5X4]
sheet 97==== Debug Interface
R9725  R / 10 / K / 0402  [R0402]
R9726  R / 10 / K / 0402  [R0402]
R9731  R / 1 / K / 0402 /NC  [R0402]
R9732  R / 1 / K / 0402 / NC  [R0402]
TP405  NC_TP30MIL  [TP20MIL]
TP406  NC_TP30MIL  [TP20MIL]
TP407  NC_TP30MIL  [TP20MIL]
TP408  NC_TP30MIL  [TP20MIL]
TP409  NC_TP30MIL  [TP20MIL]
TP410  NC_TP30MIL  [TP20MIL]
TP9707  NC  [TP50MIL]
TP9708  NC  [TP50MIL]
TP9709  NC  [TP50MIL]
TP9710  NC  [TP50MIL]
TP9711  NC  [TP50MIL]
TP9712  NC  [TP50MIL]
TP9719  NC  [TP_2.4A]
TP9720  NC  [TP_2.4A]

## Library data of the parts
R204-R206 = R_4.7_K_0402
C109 C208 = C_22_uF_0805_X5R
C114 C211 C217 C301 C314 C319 C320 C326 C394 C398 C399 = C_1000_nF_0402
C302 C304 C341 = C_4700_nF_0603
C102 C103 C305 = C_10_uF_0603_X5R
C59 C63 C306 C316 C321 C322 C325 C1018 C1023 C1130 = C_1000_nF_0402_X5R
C323 = C_2200_nF_0402_X5R
C324 = C_1000_nF_0603
D201 = D_UDZS_5.6B
J201 = VIB_Z4PC3B8129521_0
Q301 = Q_STT818B
Q302 = Q_SSM3K35MFV
R11 = R_51_K_0402
R13 = R_0_ohm_0603
R28 R232 R399 R409 = R_24_K_0402
R316 = R_20_K_0402
R319 = R_300_K_0402
R321 = R_6.8_K_0402
R325 = RESISTOR
TP18-TP22 TP301 TP305 TP9707-TP9712 TP9719 TP9720 = T_POINT_F
U9770 = BAT-CON
ANTENNA1 BT_ANT2 FM_ANT1 GSM_ANT1 = ANTENNA_0: ANTENNA; Part Type: Connector
C122 C125 = C_22_pF_0402
C128 C129 = C_6_pF_0402
C401 C501 = C_100_nF_0402_X5R
C408 = C_220_pF_0402
J401 = TST_PORT_0: CONN ANTENNA; Customer PN: 67MM8430260F; Manufacturer Part Number: MM8430-2610RB3; Part Type: Connector; Vendor: Murata
R71 R73 R84 R170-R179 R233 R234 R507 R509 = R_0_ohm_0402
R408 R9725 R9726 = R_10_K_0402
TP401-TP410 = T_POINT_F: Part Type: Misc
U1 = MT6260
U9705 = RF7163_4
X401 = TCVCXO_0: TCVCXO 26MHz; Customer PN: 70TZ1879A00F; Manufacturer Part Number: TZ1879A; Part Type: Crystal\OSC; Vendor: Taisaw
C503-C505 = C_10_pF_0402
C2000 = CAP_NP: L 3.3nH +-0.3n 0402
L37 L39 L40 L47 L501 L504 = L_1_nH_0402
L505 = L_72_nH_0603_HQ
C179 = C_2200_nF_0603
J550 = LCM_45pin_ZIF_1: PC Á¬½ÓÆ÷ 45PIN 1mm; Customer PN: KF0A45000000F; Manufacturer Part Number: FH26-45S-0.3SHW; Part Type: Connector; Vendor: Hirose
R531 R537 = R_0_ohm_0402-3P(1-2)
U15 = CM8249QR-B_2
C105 C1001 C1016 = C_33_pF_0402
C161 = CAP_NP_6: C 0.1u 10V K 0402 X5R; Material: X5R; PN: GRM36X5R104K10D641; Vendor: MURUTA
C162 = CAP_NP_1: C 33p 50V J 0402 C0G; Material: C0G
C163 = CAP_NP_5: C 33p 50V J 0402 C0G; Material: C0G
C164 = CAP_NP_4: C 100p 50V J 0402 C0G; Material: C0G
C165 = CAP_NP_7: C 0.1u 10V K 0402 X5R; Material: X5R; PN: GRM36X5R104K10D641; Vendor: MURUTA
C166 = CAP_NP_2: C 10u 6.3V Z 0805 X5R; Material: X5R; PN: GRM225Y5V106Z10; Vendor: TDK
C1002 C1005 C1006 C1027 = SMALL_CAP: C 33p 50V J 0402 C0G
C1007 = CAP_NP_3: C 47u 6.3V Z 0805 Y5V; Material: Y5V
C1010 = CAP_NP: C 47u 6.3V Z 0805 Y5V; Material: Y5V
C1013 C1014 C1028 C1029 = CAP_0402: C 33p 50V J 0402 C0G
C1020 = C_100_pF_0402
J1003 = JACK_CON_7_KJA1339C01R_0
J1004 = USB_CON_6_22AD_018
L33 L35 = INDUCTOR_FERRITE_0: BLM18PG221SH1; PN: BLM18PG221SH1; Vendor: MURATA
L38 = Inductor: L 72nH 2% 0603; PN: LQW18AN72NG00; Vendor: Murata
LS1001 = 2-PIN__0: Part Type: Connector
R86 = R: R 1K J 1/16W 0402; PN: RR0510S-102-J; Vendor: CYNTEC
R87 = R_3: R 1.5K J 1/16W 0402; PN: RR0510S-152-J; Vendor: CYNTEC
R145 R146 R238 R239 R1200 R9731 R9732 = R_1_K_0402
R1006 = R_4: R 1K J 1/16W 0402
R1096 = R_2: R 330 J 1/16W 0402; PN: RR0510S-240-J; Vendor: CYNTEC
R1097 = R_1: R 330 J 1/16W 0402; PN: RR0510S-240-J; Vendor: CYNTEC
U9709-U9712 = pad1
U1109 = CONN_4PIN
U9715 U9716 = SIM
U9717 = T-card
U9720 U9736 U9751 = key_2
U9721 U9738-U9750 U9752 U9759 U9765-U9768 = key_3
U9753-U9758 = LED_1

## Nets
GND_SIGNAL: C59.2 C63.2 C102.2 C103.2 C109.2 C114.2 C128.2 C129.2 C162.2 C163.2 C166.2 C179.2 C208.1 C211.2 C217.2 C301.2 C302.2 C305.2 C306.2 C314.2 C316.2 C319.2 C320.2 C321.2 C322.2 C323.2 C324.2 C325.2 C326.2 C341.2 C394.2 C399.2 C401.2 C408.2 C501.2 C504.1 C1001.2 C1005.2 C1006.2 C1013.1 C1014.1 C1016.2 C1028.1 C1029.1 C1130.2 D201.1(ANODE) GSM_ANT1.1 J201.2(-) J401.3(GND) J401.4(GND) J401.5(GND) J401.6(GND) J550.1(GND) J550.13(IM2) J550.54(GND) J1004.4(GND) J1004.5(GND) J1004.6(GND) L38.2 L504.2 L505.2 R11.2 R146.2 R204.2 R232.1 R234.2 R409.2 R509.1 R531.3 R537.1 R9725.2 R9726.2 U1.A1(AVSS_2G) U1.A3(RXLB_N) U1.A5(AVSS_2G) U1.A19(GND) U1.B2(RXHB_N) U1.B7(AVSS_BT) U1.C3(AVSS_2G) U1.C7(CLK_SEL) U1.C8(AVSS_BT) U1.D1(AVSS_2G) U1.D2(AVSS_2G) U1.D4(AVSS_2G) U1.E5(AVSS43_PMU) U1.E7(AVSS_2G) U1.G4(TESTMODE) U1.G5(AGND) U1.G10(GND) U1.G12(GND) U1.G19(GND) U1.H11(GND) U1.J7(AVSS43_PMU) U1.J10(GND) U1.J12(GND) U1.K4(AVSS43_CP) U1.K7(AVSS43_PMU) U1.L4(AVSS43_SPK) U1.L5(AVSS43_PMU) U1.M6(AVSS43_PMU) U1.M18(GND) U1.M19(GND) U1.T10(AVSS_FM) U1.U4(AVSS28_ABB) U1.U12(GND) U1.U19(GND) U15.8(DGND) U15.10(DGND) U15.12(DGND) U9705.1(GND) U9705.2(GND) U9705.4(GND) U9705.6(GND) U9705.7(GND) U9705.8(GND) U9705.9(GND) U9705.10(NC) U9705.13(NC) U9705.15(GND) U9705.16(GND) U9705.17(NC) U9705.23(GND) U9715.3(GND) U9715.7(GND) U9715.8(GND) U9715.9(GND) U9715.10(GND) U9716.3(GND) U9716.7(GND) U9716.8(GND) U9716.9(GND) U9716.10(GND) U9717.6(VSS) U9717.9(GND) U9717.10(GND) U9717.11(GND) U9717.12(GND) U9738.1 U9770.2(GND) U9770.4(GND) U9770.5(GND) X401.2(GND) X401.4(GND)
VBAT: C109.1 C179.1 C301.1 C321.1 C322.1 C326.1 C341.1 D201.2(CATHODE) J550.55(LEDA) R13.1 R174.1 R175.1 R176.1 R177.1 R178.1 R179.1 TP19.1(TP) U1.E3(VBAT_VA) U1.F6(BATSNS) U1.L3(AVDD43_CP) U1.U9(VBAT_DIGITAL) U9705.18(VBATT) U9770.3(VBAT)
ACCDET: R1006.2 U1.N3(ACCDET)
ANT_2G: ANTENNA1.1 C129.1 R84.1
ANT_2G_1: C128.1 J401.2(IN) R84.2
ANT_2G_2: J401.1(OUT) U9705.14(ANTENNA)
APC_VBIAS: R408.2 U1.P1(APC)
AU_OUT0_N: C1027.1 C1029.2 U1.R5(HSN) U9710.1
AU_OUT0_P: C1027.2 C1028.2 U1.P5(HSP) U9709.1
BACKUP: R316.2 U1.K9(XTAL_SEL) U1.L8(VRTC)
BANDSW: U1.C10(BPI_BUS0) U9705.20(GPCTRL0)
BATDET: R28.2 U1.J2(BATDET)
BATON: R399.2 U1.J6(BATON)
BPI_BUS1: R9726.1 R9731.2 U1.C9(BPI_BUS1)
BT_LNA: C2000.2 U1.B8(BT_LNA)
CHR_LDO: C325.1 Q302.1(G) R321.2 U1.J3(CHR_LDO)
CMDAT0: TP407.1(TP) U1.B14(CMDAT0) U15.24(D0)
CMDAT1: TP408.1(TP) U1.E12(CMDAT1) U15.23(D1)
CMDAT2: TP409.1(TP) U1.C13(CMDAT2) U15.22(D2)
CMDAT3: TP405.1(TP) U1.B13(CMDAT3) U15.21(D3)
CMDAT4: TP410.1(TP) U1.B15(CMDAT4) U15.20(D4)
CMDAT5: TP406.1(TP) U1.A15(CMDAT5) U15.19(D5)
CMDAT6: U1.D12(CMDAT6) U15.18(D6)
CMDAT7: U1.C15(CMDAT7) U15.17(D7)
CMHREF: U1.E11(CMHREF) U15.2(HREF)
CMMCLK: U1.A17(CMMCLK) U15.11(XCLK1)
CMPCLK: U1.A12(CMPCLK) U15.9(PCLK)
CMPDN: U1.A14(CMPDN) U15.1(PWDN)
CMRST: R204.1 U1.B12(CMRST) U15.4(RESET)
CMVREF: U1.B16(CMVREF) U15.3(VSYNC)
DRV: Q302.2(S) U1.J1(DRV)
EAR_EINT: R238.1 TP403.1(TP) U1.C5(TP3)
FLYN: C304.1 U1.K1(FLYN)
FLYP: C304.2 U1.K2(FLYP)
FM_ANT-N: R146.1 R509.2 U1.T11(FM_ANT_N)
FM_ANT-P: L505.1 R145.1 R507.1 U1.U11(FM_ANT_P)
ISENSE: Q301.1(C) Q301.2(C) Q301.5(C) Q301.6(C) R13.2 U1.G6(ISENSE)
ISINK0: J550.56(LEDK1) U1.G2(ISINK0)
ISINK1: J550.57(LEDK2) U1.G3(ISINK1)
ISINK2: J550.58(LEDK3) U1.H2(ISINK2)
ISINK3: J550.59(LEDK4) U1.H3(ISINK3)
KCOL0: R170.2 TP22.1(TP) U1.E17(KCOL0) U9720.2
KCOL1: R171.2 U1.A18(KCOL1) U1109.4 U9744.2 U9765.2 U9767.2
KCOL2: R172.2 U1.E18(KCOL2) U1109.3 U9736.2 U9740.2 U9742.2
KCOL3: R173.2 U1.F17(KCOL3) U1109.2 U9746.2 U9748.2 U9751.2
KPLED: U1.H1(KPLED) U9753.1(-) U9754.1(-) U9755.1(-) U9756.1(-) U9757.1(-) U9758.1(-)
KROW0: U1.C17(KROW0) U9720.1 U9721.1 U9736.1 U9739.1 U9744.1 U9750.1 U9751.1 U9759.1
KROW1: U1.C14(KROW1) U9740.1 U9741.1 U9746.1 U9747.1 U9765.1 U9766.1
KROW2: U1.C16(KROW2) U9742.1 U9743.1 U9748.1 U9749.1 U9767.1 U9768.1
KROW3: U1.D18(KROW3) U1109.1 U9745.1 U9752.1
LCD_BS0: J550.11(IM0) R531.2
LCD_BS1: J550.12(IM1) R537.2
LPA0: J550.42(RS) U1.K16(LPA0)
LPCE0_B: J550.43(CS) U1.L18(LPCE0_B)
LPRSTB: J550.15(RESET) U1.K18(LPRSTB)
LPTE: J550.10(TE) U1.J17(LPTE)
LRD_B: J550.40(RD) U1.L17(LRD_B)
LWR_B: J550.41(WR) U1.L16(LWR_B)
MCCK: TP9707.1(TP) U1.U18(MCCK) U9717.5(CLK)
MCCM0: TP9708.1(TP) U1.T17(MCCM0) U9717.3(CMD)
MCDA0: TP9712.1(TP) U1.T16(MCDA0) U9717.7(DAT0)
MCDA1: TP9709.1(TP) U1.T18(MCDA1) U9717.8(DAT1)
MCDA2: TP9710.1(TP) U1.U17(MCDA2) U9717.1(DAT2)
MCDA3: TP9711.1(TP) U1.R17(MCDA3) U9717.2(DAT3)
MICBIAS0: R73.2 U1.R2(AU_MICBIAS0)
MICBIAS1: R86.2 U1.P2(AU_MICBIAS1)
MICN0: C1023.2 U1.U1(AU_VIN0_N)
MICN1: C165.1 U1.T2(AU_VIN1_N)
MICP0: C1018.2 U1.T1(AU_VIN0_P)
MICP1: C161.1 U1.U2(AU_VIN1_P)
MP3_OUTL: C1007.1 U1.T5(HPL)
MP3_OUTR: C1010.1 U1.U5(HPR)
NLD0: J550.39(DB0) U1.G17(NLD0)
NLD1: J550.38(DB1) U1.G16(NLD1)
NLD2: J550.37(DB2) U1.H17(NLD2)
NLD3: J550.36(DB3) U1.J18(NLD3)
NLD4: J550.35(DB4) U1.K17(NLD4)
NLD5: J550.34(DB5) U1.N18(NLD5)
NLD6: J550.33(DB6) U1.K19(NLD6)
NLD7: J550.32(DB7) U1.H16(NLD7)
NLD8: J550.31(DB8) U1.J19(NLD8)
PWRKEY: R1200.2 TP18.1(TP) U1.H4(PWRKEY)
RESETB: R325.1 U1.K10(RESETB)
RX_HB: C125.1 U9705.11(RX0)
RX_LB: C122.1 U9705.12(RX1)
RXHB_P: C125.2 U1.B1(RXHB_P)
RXLB_P: C122.2 U1.A2(RXLB_P)
SCL28: R205.2 U1.D16(SCL28) U15.14(SIO-C)
SDA28: R206.2 U1.F18(SDA28) U15.13(SIO-D)
SIM1_EINT: TP402.1(TP) U1.B4(TP2)
SIM1_SCLK: U1.U14(SIM1_SCLK) U9715.6(CLK)
SIM1_SIO: U1.R14(SIM1_SIO) U9715.1(I/O)
SIM1_SRST: U1.T14(SIM1_SRST) U9715.5(RST)
SIM2_SCLK: U1.U16(SIM2_SCLK) U9716.6(CLK)
SIM2_SIO: U1.R15(SIM2_SIO) U9716.1(I/O)
SIM2_SRST: U1.T15(SIM2_SRST) U9716.5(RST)
SPKN0: C1002.1 C1005.1 L33.1 U1.M2(SPK_OUTN)
SPKP0: C1002.2 C1006.1 L35.1 U1.M1(SPK_OUTP)
TP1: TP401.1(TP) U1.C4(TP1)
TP4: TP404.1(TP) U1.B5(TP4)
TR_SW_EN: R9725.1 R9732.2 U1.D11(BPI_BUS3) U9705.19(GPCTRL1)
TX_EN: U1.D9(BPI_BUS2) U9705.21(TX_ENABLE)
TX_VRAMP: C408.1 R408.1 R409.1 U9705.22(VRAMP)
TXO_HB: U1.C2(TXO_HB) U9705.3(RFIN_HB)
TXO_LB: U1.C1(TXO_LB) U9705.5(RFIN_LB)
URXD1: TP9720.1(TP) U1.C11(URXD1)
USB_DM: J1004.2(USB_DN) TP20.1(TP) U1.U13(USB11_DM)
USB_DP: J1004.3(USB_DP) TP21.1(TP) U1.T13(USB11_DP)
UTXD1: TP9719.1(TP) U1.B10(UTXD1)
VA: C401.1 U1.F9(AVDD28_2GAFE) U1.U6(VA)
VBOOST: C302.1 C305.1 TP301.1(TP) U1.L2(VBOOST) U1.M3(VBAT_SPK)
VCAMA: C103.1 C114.1 U1.E1(VCAMA) U1.T12(AVDD28_FM) U15.7(AVDD)
VCAMD: C102.1 U1.F2(VCAMD) U15.6(DOVDD)
VCDT: R11.1 R319.2 U1.J4(VCDT)
VCHG: C324.1 J1004.1(VBUS) Q301.4(E) R319.1 R321.1
VCORE: C323.1 U1.F10(VDDK) U1.K12(VDDK) U1.T9(VCORE)
VIBR: C306.1 J201.1(+) U1.T6(VIBR)
VIO18: C320.1 J550.8(IOVCC) R531.1 R537.3 U1.F14(DVDD18_EMI) U1.F15(DVDD18_EMI) U1.T8(VIO18)
VIO28: C217.1 C394.1 C501.1 J550.6(VCC) J550.7(VCC) R205.1 R206.1 R239.2 R325.2 R9731.1 R9732.1 U1.A9(DVDD28) U1.B9(DVDD28_FSRC) U1.D14(DVDD28) U1.U8(VIO28)
VMC: C319.1 C1130.1 U1.R8(VMC) U1.R16(DVDD33_MSDC) U9717.4(VDD)
VREF: C316.1 U1.F4(VREF)
VRF: C399.1 U1.E2(VRF)
VSF: C211.1 TP305.1(TP) U1.M16(DVDD28_SF) U1.R7(VSF)
VSIM1: C59.1 U1.N10(VSIM1) U9715.2(VPP) U9715.4(VCC)
VSIM2: C63.1 U1.N9(VSIM2) U9716.2(VPP) U9716.4(VCC)
VUSB: C314.1 U1.N8(VUSB)
XM: J550.5(XL) U1.T4(XM)
XMIC: C161.2 C163.1 C164.2 L37.1 R87.1 R1006.1
XMP3_L: C1014.2 L40.1 R1097.1
XMP3_R: C1013.2 L39.1 R1096.1
XP: J550.3(XR) U1.R3(XP)
XTAL1: U1.A6(XTAL1) X401.1(HOT)
XTAL2: U1.B6(XTAL2) X401.3(HOT)
YM: J550.4(YD) U1.U3(YM)
YP: J550.2(YU) U1.T3(YP)
N23513658: Q301.3(B) Q302.3(D)
N38630034: R28.1 R232.2 R399.1 U9770.1(NC)
N38884227: C208.2 R316.1
N43334462: C162.1 C164.1 C165.2 C166.1 R86.1 R87.2
N43335305: L33.2 LS1001.2(N)
N43335313: L35.2 LS1001.1(P)
N44219572: FM_ANT1.1 R507.2
N44460338: C1007.2 R1097.2
N44461577: C1010.2 R1096.2
N46222451: J1003.1(GND) L38.1 R145.2
N46222453: J1003.3(SPKR) L39.2
N46222455: J1003.2(SPKL) L40.2
N46228101: J1003.6(MIC+) L37.2
N46369627: C1001.1 C1020.1 C1023.1 R233.1 U9711.1
N46383379: C1016.1 C1018.1 C1020.2 R71.1 U9712.1
N46384666: C105.1 R71.2 R73.1
N46386914: C105.2 R233.2 R234.1
N46546133: R170.1 U9721.2
N46562969: R171.1 U9759.2 U9766.2 U9768.2
N46588950: R172.1 U9739.2 U9741.2 U9743.2 U9745.2
N46608835: R173.1 U9747.2 U9749.2 U9750.2 U9752.2
N46633108: R1200.1 U9738.2
N47310385: L47.1 R238.2 R239.1
N47311487: J1003.4(NC) L47.2
N47430056: C503.1 C2000.1 L501.1
N47430141: BT_ANT2.1 C503.2 C505.2
N47700303: R177.2 U9756.2(+)
N47700304: R174.2 U9753.2(+)
N47700305: R178.2 U9757.2(+)
N47700307: R175.2 U9754.2(+)
N47700308: R179.2 U9758.2(+)
N47700309: R176.2 U9755.2(+)
N47770986: C505.1 L504.1
N47772094: C504.2 L501.2

Not connected (* = marked no-connect by the designer): C398 1 2; J550 9(BLU_PWM)* 14(IM3)* 16(DB23)* 17(DB22)* 18(DB21)* 19(DB20)* 20(DB19)* 21(DB18)* 22(DB17)* 23(DB16)* 24(DB15)* 25(DB14)* 26(DB13)* 27(DB12)* 28(DB11)* 29(DB10)* 30(DB9)* 44(SDI)* 45(SDO)* 46(VSYNC)* 47(HSYNC)* 48(ENABLE)* 49(DOTCLK)* 50(STB_CLKP)* 51(STB_CLKN)* 52(DATA_ON)* 53(DATA_OP)* 60(LEDK5)* 61(LEDK6)*; J1003 5(NC)* 7(NC)*; U1 A11(URXD2) B11(UTXD2) B17(GPIO19) B18(GPIO17) B19(GPIO16) C18(KCOL4) C19(EDICK) D6(FREF1) D17(KROW4) D19(EDIWS) F16(WATCHDOG) F19(EDIDAT) H18(LSRSTB) J9(SRCLKENAI) J16(LSCE1_B) L9(XIN) L10(XOUT) M17(LPCE1_B) N16(NC) N17(NC) P17(NC) P18(NC) P19(MCINS) R1(AUX_IN4) R18(NC) R19(NC) T19(NC); U15 5(DVDD) 15(D9)* 16(D8)*

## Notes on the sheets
sheet 2
- LOUD SPEAKER
- Audio
- HEADSET MICOPHONE
- HEADSET EarPhone
- This ESD components are optional for better ESD performance
  NOTE: 1. Total C load of Audio output must < 330pf and close to JACK
              2. For DC couple case please choose Bi-direction component
- Close to chip
- Shieding ¤º
- »PHeadSet)ªº¸¨¦aÂI
  ¬Û±µ«á¦A±µ¨t²Î¤j¦a
- ±µ¦b¤@°_«á¸¨¨t²Î¤j¦a
- Shieding ¤º
- HOOK DETECTION
- ±µ¦b¤@°_«á¸¨¨t²Î¤j¦a
- USB
- HANDSET MICOPHONE
- Close to BB
- This ESD components are optional for better ESD performance
  NOTE: 1. Total C load of Audio output must < 330pf and close to JACK
              2. For DC couple case please choose Bi-direction component
- These ESD component
  for better ESD  performance
- This ESD components are optional for better ESD performance
  NOTE: 1. C load must < 3pf and close to JACK
- This ESD components are optional for better ESD performance
  NOTE: 1. Total C load of Audio output must < 330pf and close to JACK
              2. For DC couple case please choose Bi-direction component
- HANDSET RECEIVER
- Normally open AUDIO jack , need not pull down resistor .
- Normally short  AUDIO jack , need  pull down 10K resistor .
- ±µ¦b¤@°_«á¸¨¨t²Î¤j¦a
- This serial component are optional for better FM de-sense performance
sheet 3
- History
- Date
- Version
- Owner
- Description
- Note
sheet 4
- CMRST(HW trapping PIN):
   USB 2VCOM
  0: disabled(default)
  1: enabled
- CAMERA
- KEY
- UART
- SD I/F
- I2C
- USB
- LCD interface
- TP
- SYS CTL
sheet 5
- All Charge Pump  GND "Must Be" directly to
  a non-fractured GND plane !!
- Charge Pump
- Audio
- 25mils
- 25mils
- Three CAP
  close to MT6260
- 25mils
- 25mils
- Vibrator
- shieding case ¥~
- VBAT IN
- charge pump close to MT6260
- PMU LDO
- shieding case ¥~
- close to MT6260 each power in ball
- This Two Cap(1uF) are optional
  for better power performance
- POWER IN , SF POWER , PSRAM POWER
- FM de-sense issue
- close to MT6260
  each LDO out ball
- This RC are optional for better
  FM de-sense performance
- shieding case ¥~
- This Cap (10pF) are optional
  for better BT de-sense performance
- GND­nª`·N
- CHARGE
- shieding case ¥~
- CHRIN max. 8.0V when U290 NC
- close to MT6260 each power in ball
- SIM
- ­@À£+16V
- 40mils
- This Cap shoud be
  placed  near BB
- 40mils
- Place this resister close to battery
  connector, and SNS trace should be 4mil~6mil,
  and others are 40mils
- SYSTEM CONTROL
- LED DRV
- This Cap shoud be placed  near BB
- XTAL_SEL : VRTC domain
  1: f32k_ck src INT clock source
- This TVS are optional
  for better ESD performance
- This CAP(330pF) are optional
  for better ESD performance
sheet 6
- KEY
- SIM
- Default : 2 SIM
- This ESD components are optional
  for better ESD performance
- This Caps are optional for better RF de-sense performanceC load on trace <45pF)
- SD I/F
- This Caps are optional for better ESD and RF de-sense performance,(C load on trace <15pF)
sheet 7
- LCM (Parallel Serial co-exist)
- CAMERA
- This Cap(1nF) are optional for better
  ESD performance
- reserve for ESD soloution
  close to cam connector
- In LCM interface we can config parallel interface (left-hand side  column) to serial interface (right-hand side column).
  In another word LCM serial and parallel co layout can be realized in MT6260 solution.
- Camera Interface fix 2.8V
- This Caps are optional for better
  ESD and de-sense performance
- This serial R are optional for better
  ESD performance
- VCAMD ¥²¶·¬°2.8V
- VCAMA ¥²¶·¬°2.8V
sheet 8
- 2G RF
- Shieding ¤º all RF sheet
- This Two Cap(100nF and 22pF) are optional
  for better RF performance
- This pairs of RC-filter are optional
  for better RF de-sense performance
- FM
- 26M
- All block close to MT6260
- Close to IC
- ¡¹ DCXO(X'tal)               : CLK_SEL= GND_RF
  ¡¹ Co-clock(ext CLK)  : CLK_SEL= DVDD28_IO
- AVSS_BT connected together then connect to main ground.
- This R is optional
  for better FM de-sense performance
- Single-End
- This pairs of filter are optional
  for better RF performance
- POWER IN
- JTAG Trapping
- close to MT6260 each power in ball
- shieding case ¥~
sheet 9
- Close to IC
- 50ohm
- 50ohm match
- For BT ANT matching
- These two cap are optional for better BT performance (Matching)
- PASS SIG spec must need LC filter
- Close to IC
- Close to IC
- These  are optional
  for better FM de-sense performance
sheet 10
- MCU JTAG Trapping
- Design output low(JTAG trap)
  (BPI_BUS1 , BPI_BUS3 )  00 : X
  (BPI_BUS1 , BPI_BUS3 )  01 : KEYPAD
  (BPI_BUS1 , BPI_BUS3 )  10 : MSDC
  (BPI_BUS1 , BPI_BUS3 )  11 : CAM
